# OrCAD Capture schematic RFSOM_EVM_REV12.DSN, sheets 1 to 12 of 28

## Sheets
1 01 POWER_TREE: rev: V1.2
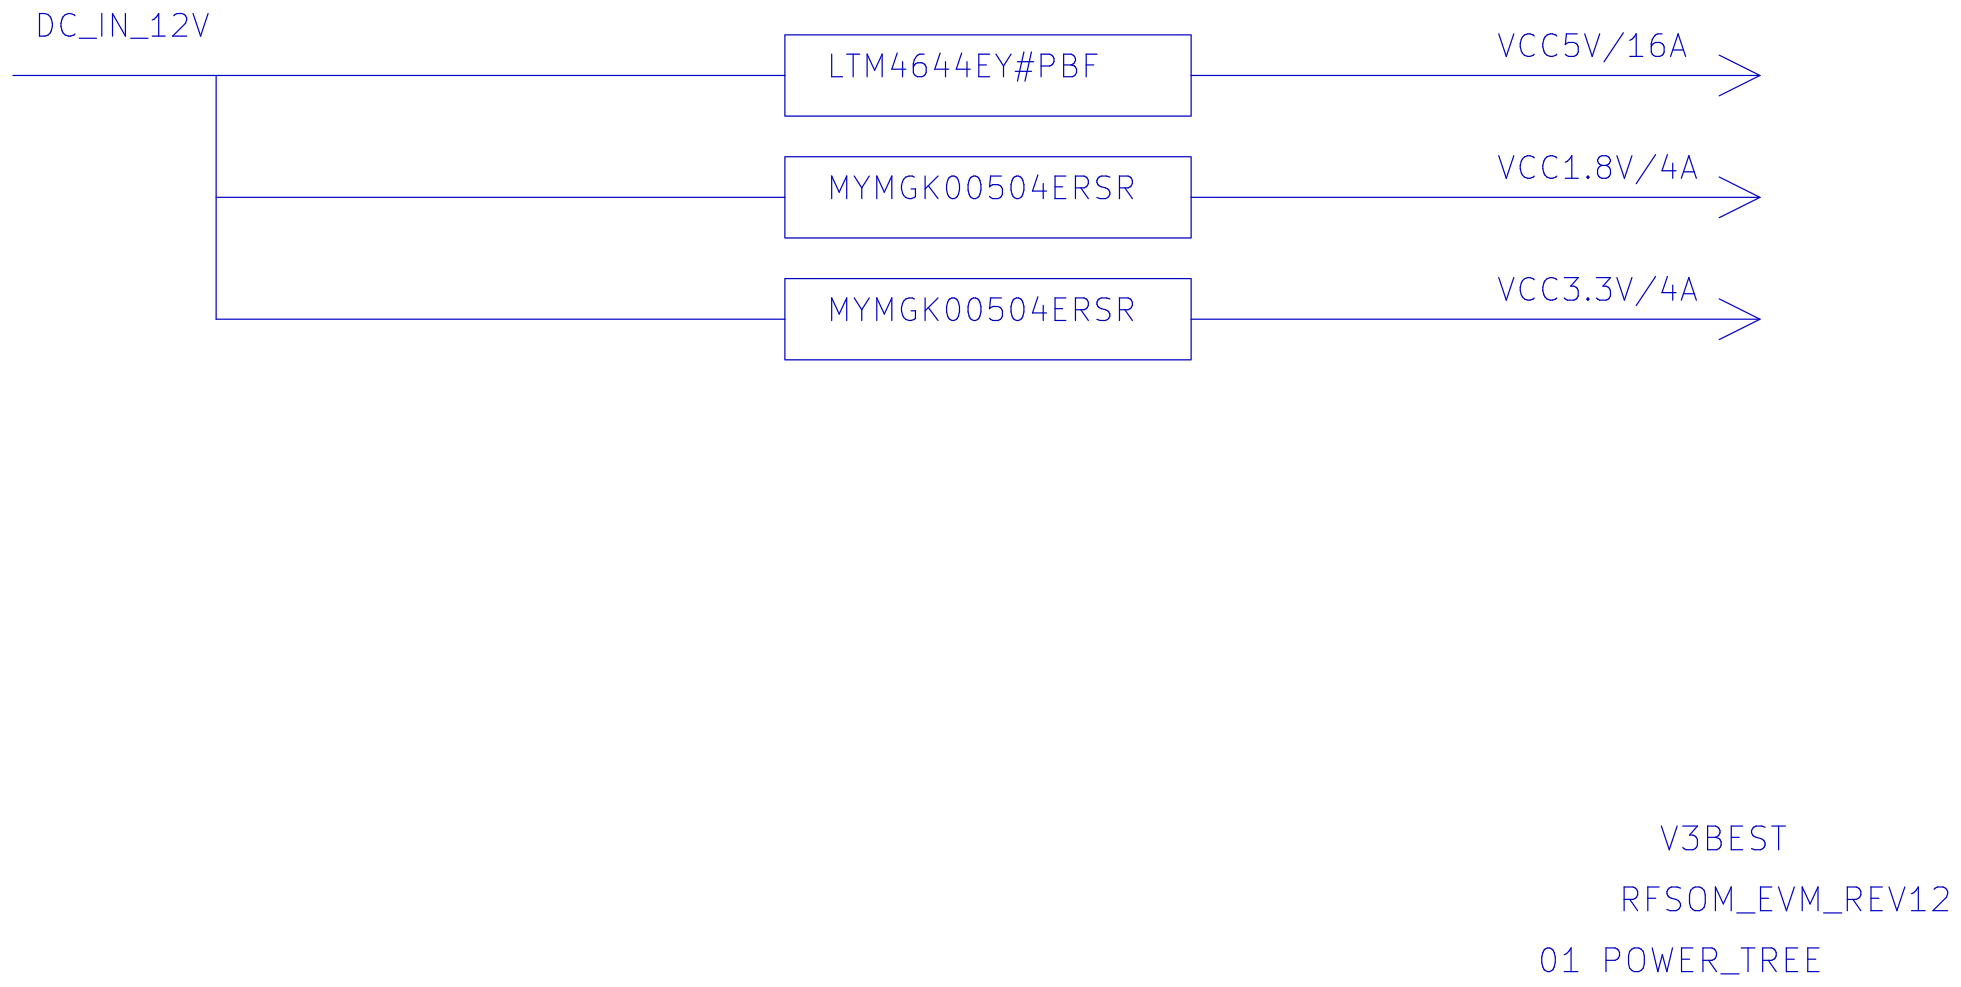
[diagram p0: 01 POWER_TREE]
2 20 ETHERNET: size A4
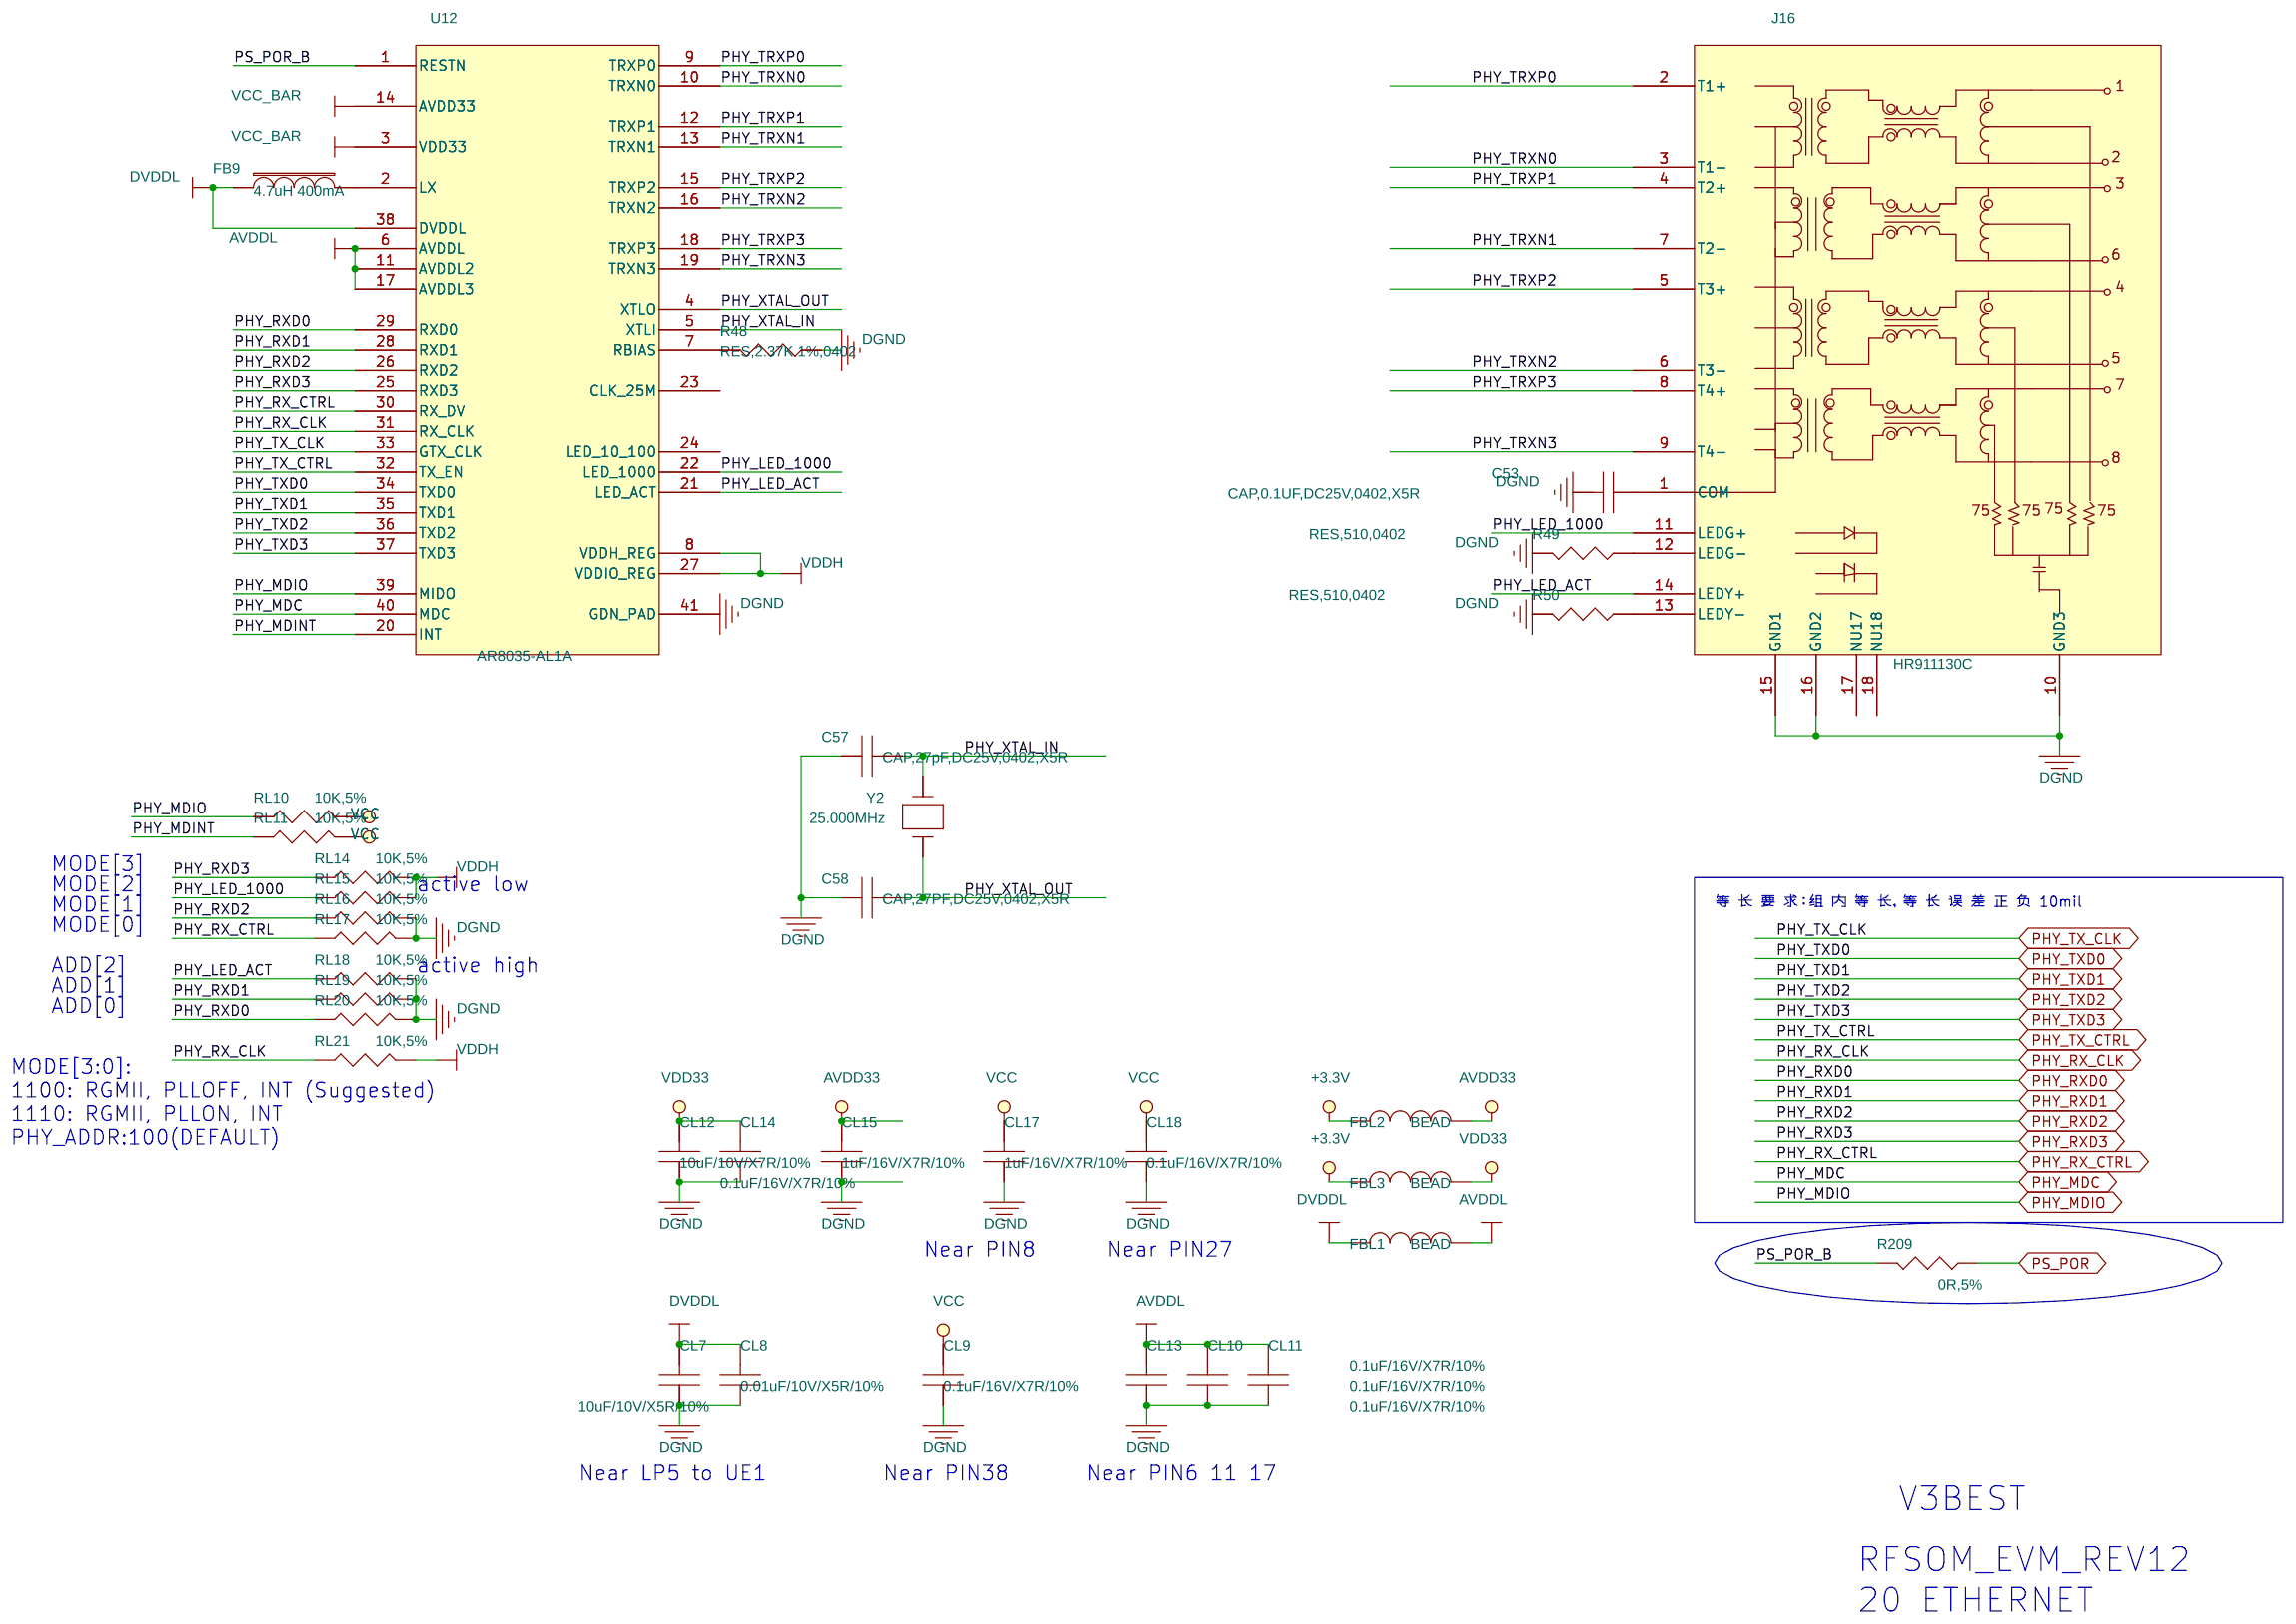
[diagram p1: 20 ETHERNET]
3 19 SFP_SG: size A4
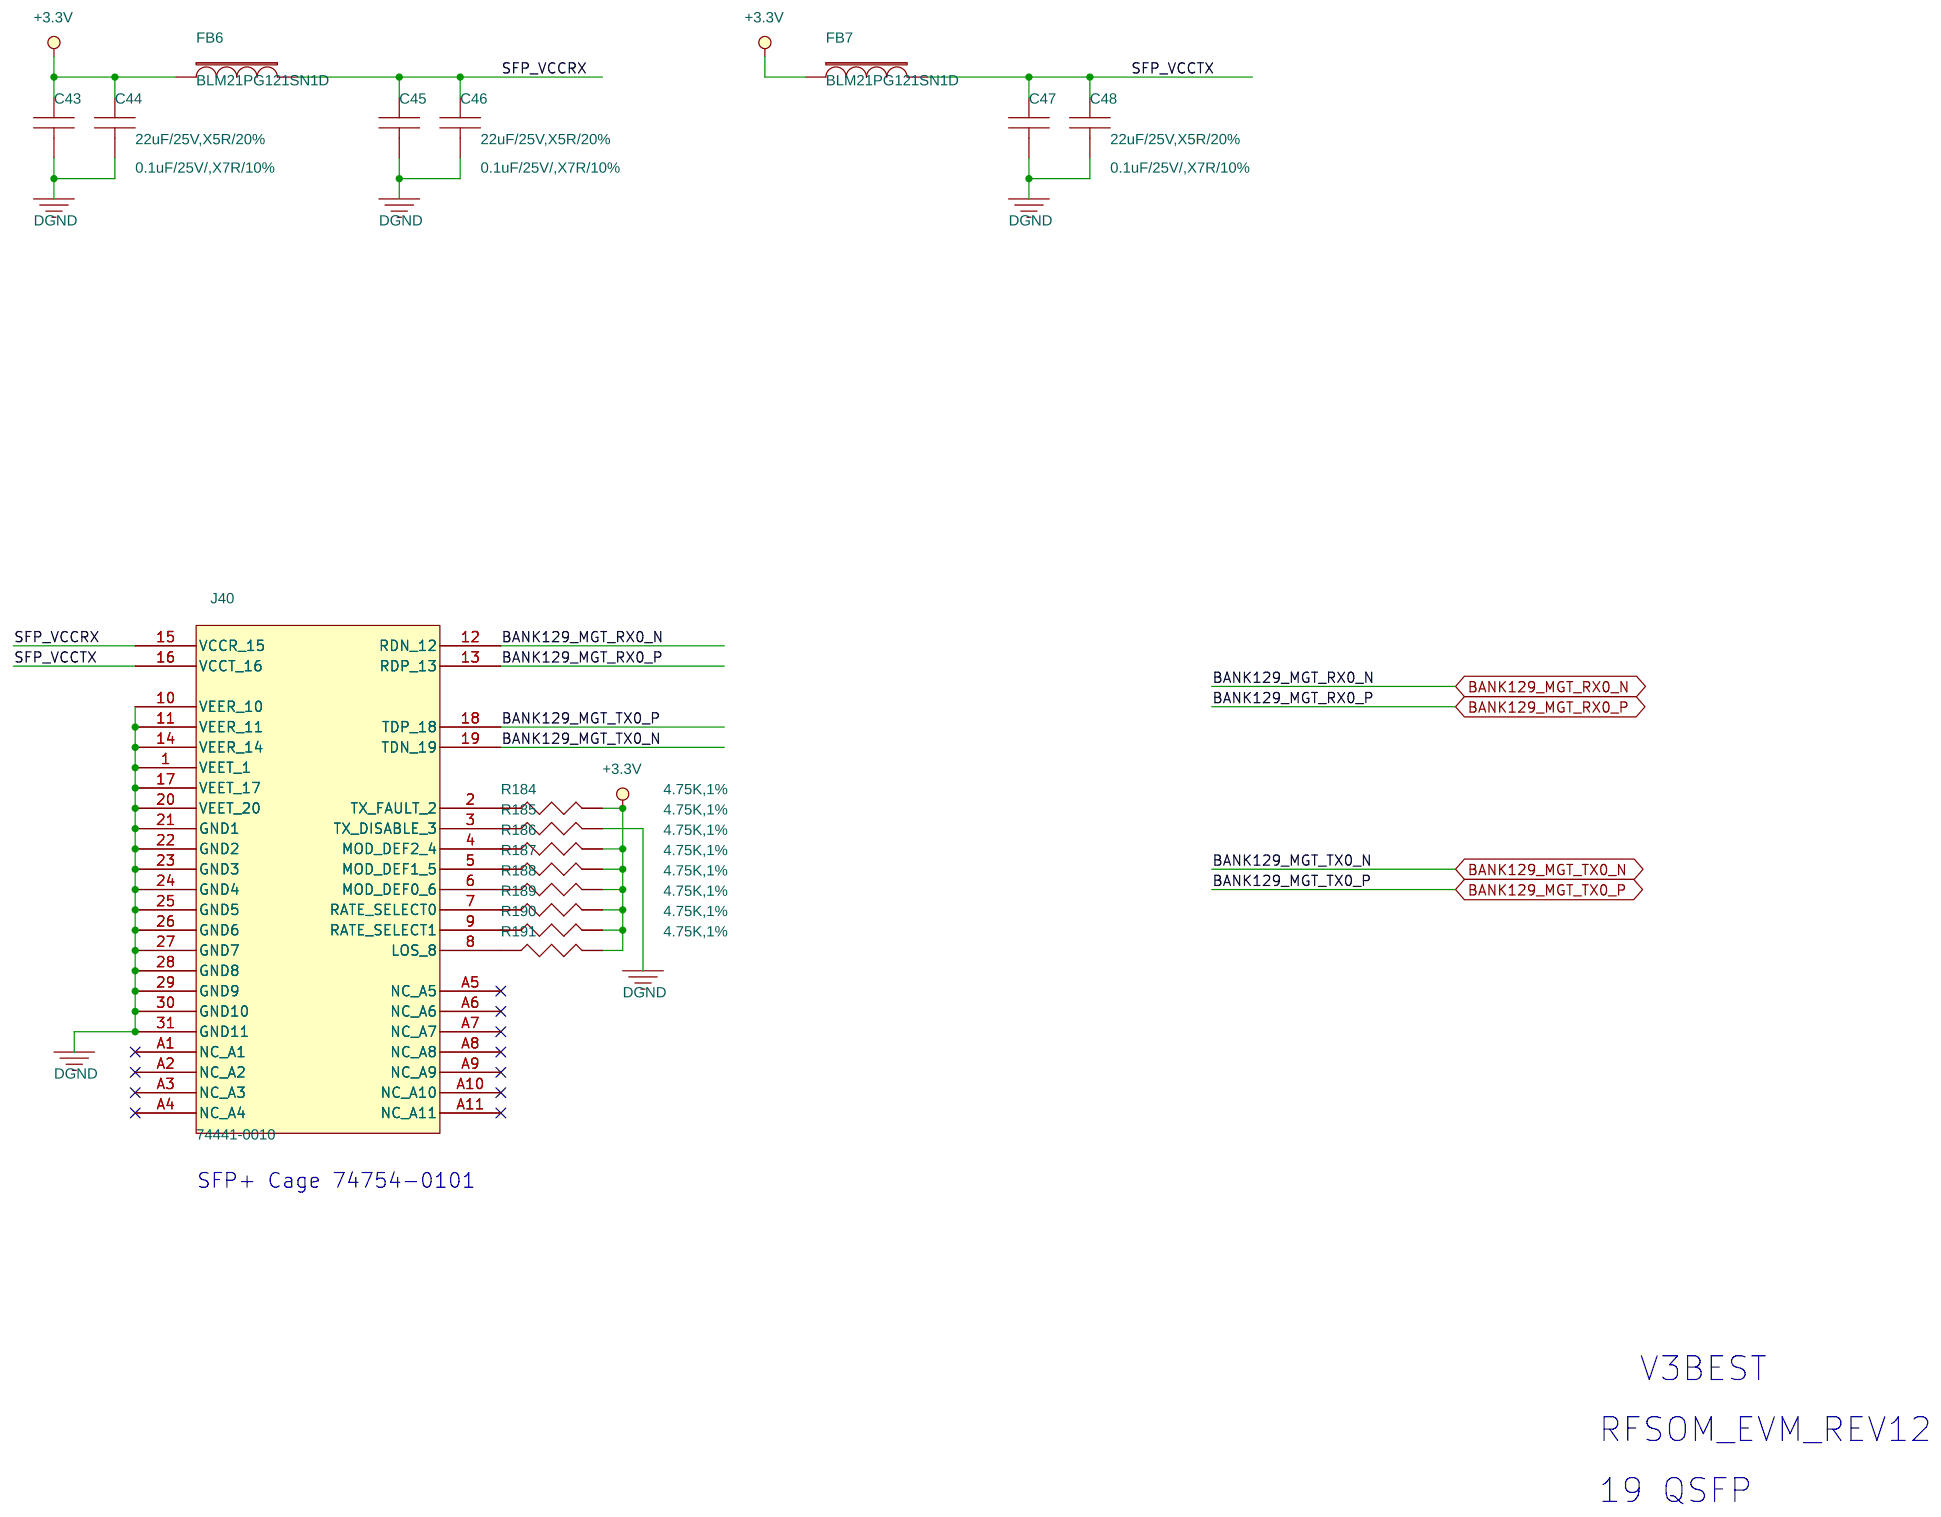
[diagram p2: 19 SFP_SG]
4 27 POWER02: size A4
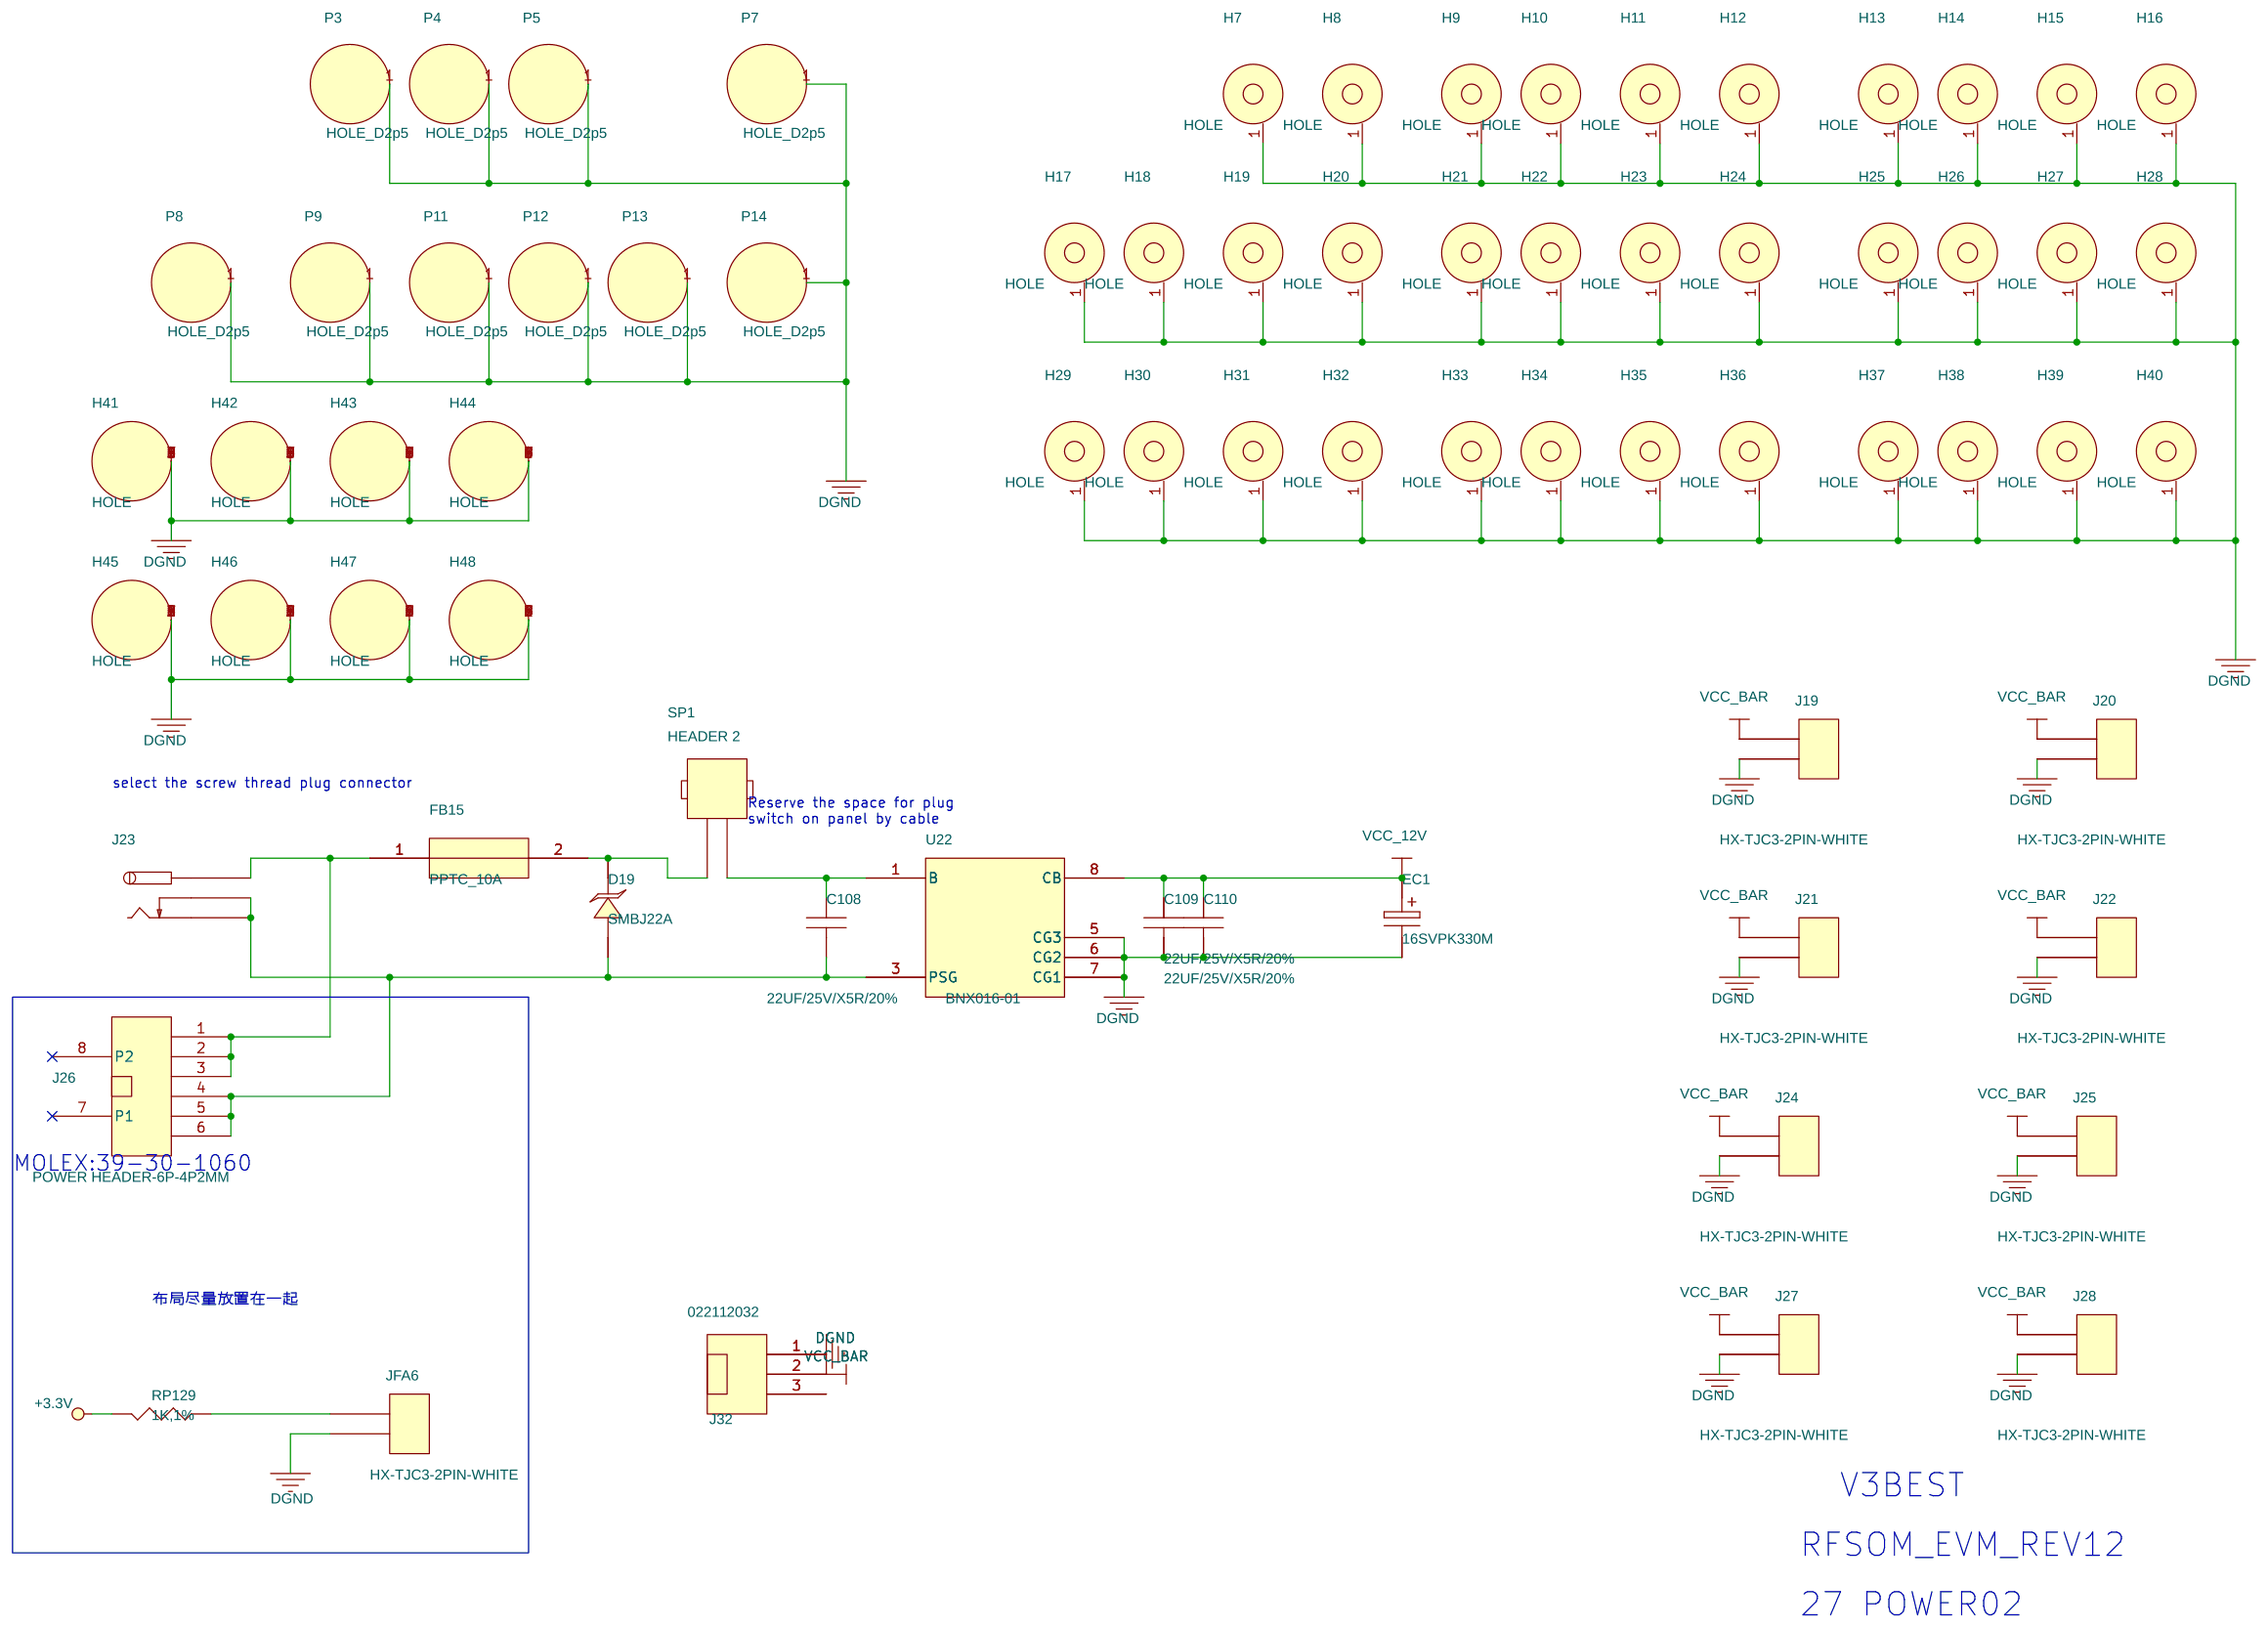
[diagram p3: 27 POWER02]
5 26 POWER01: size A4
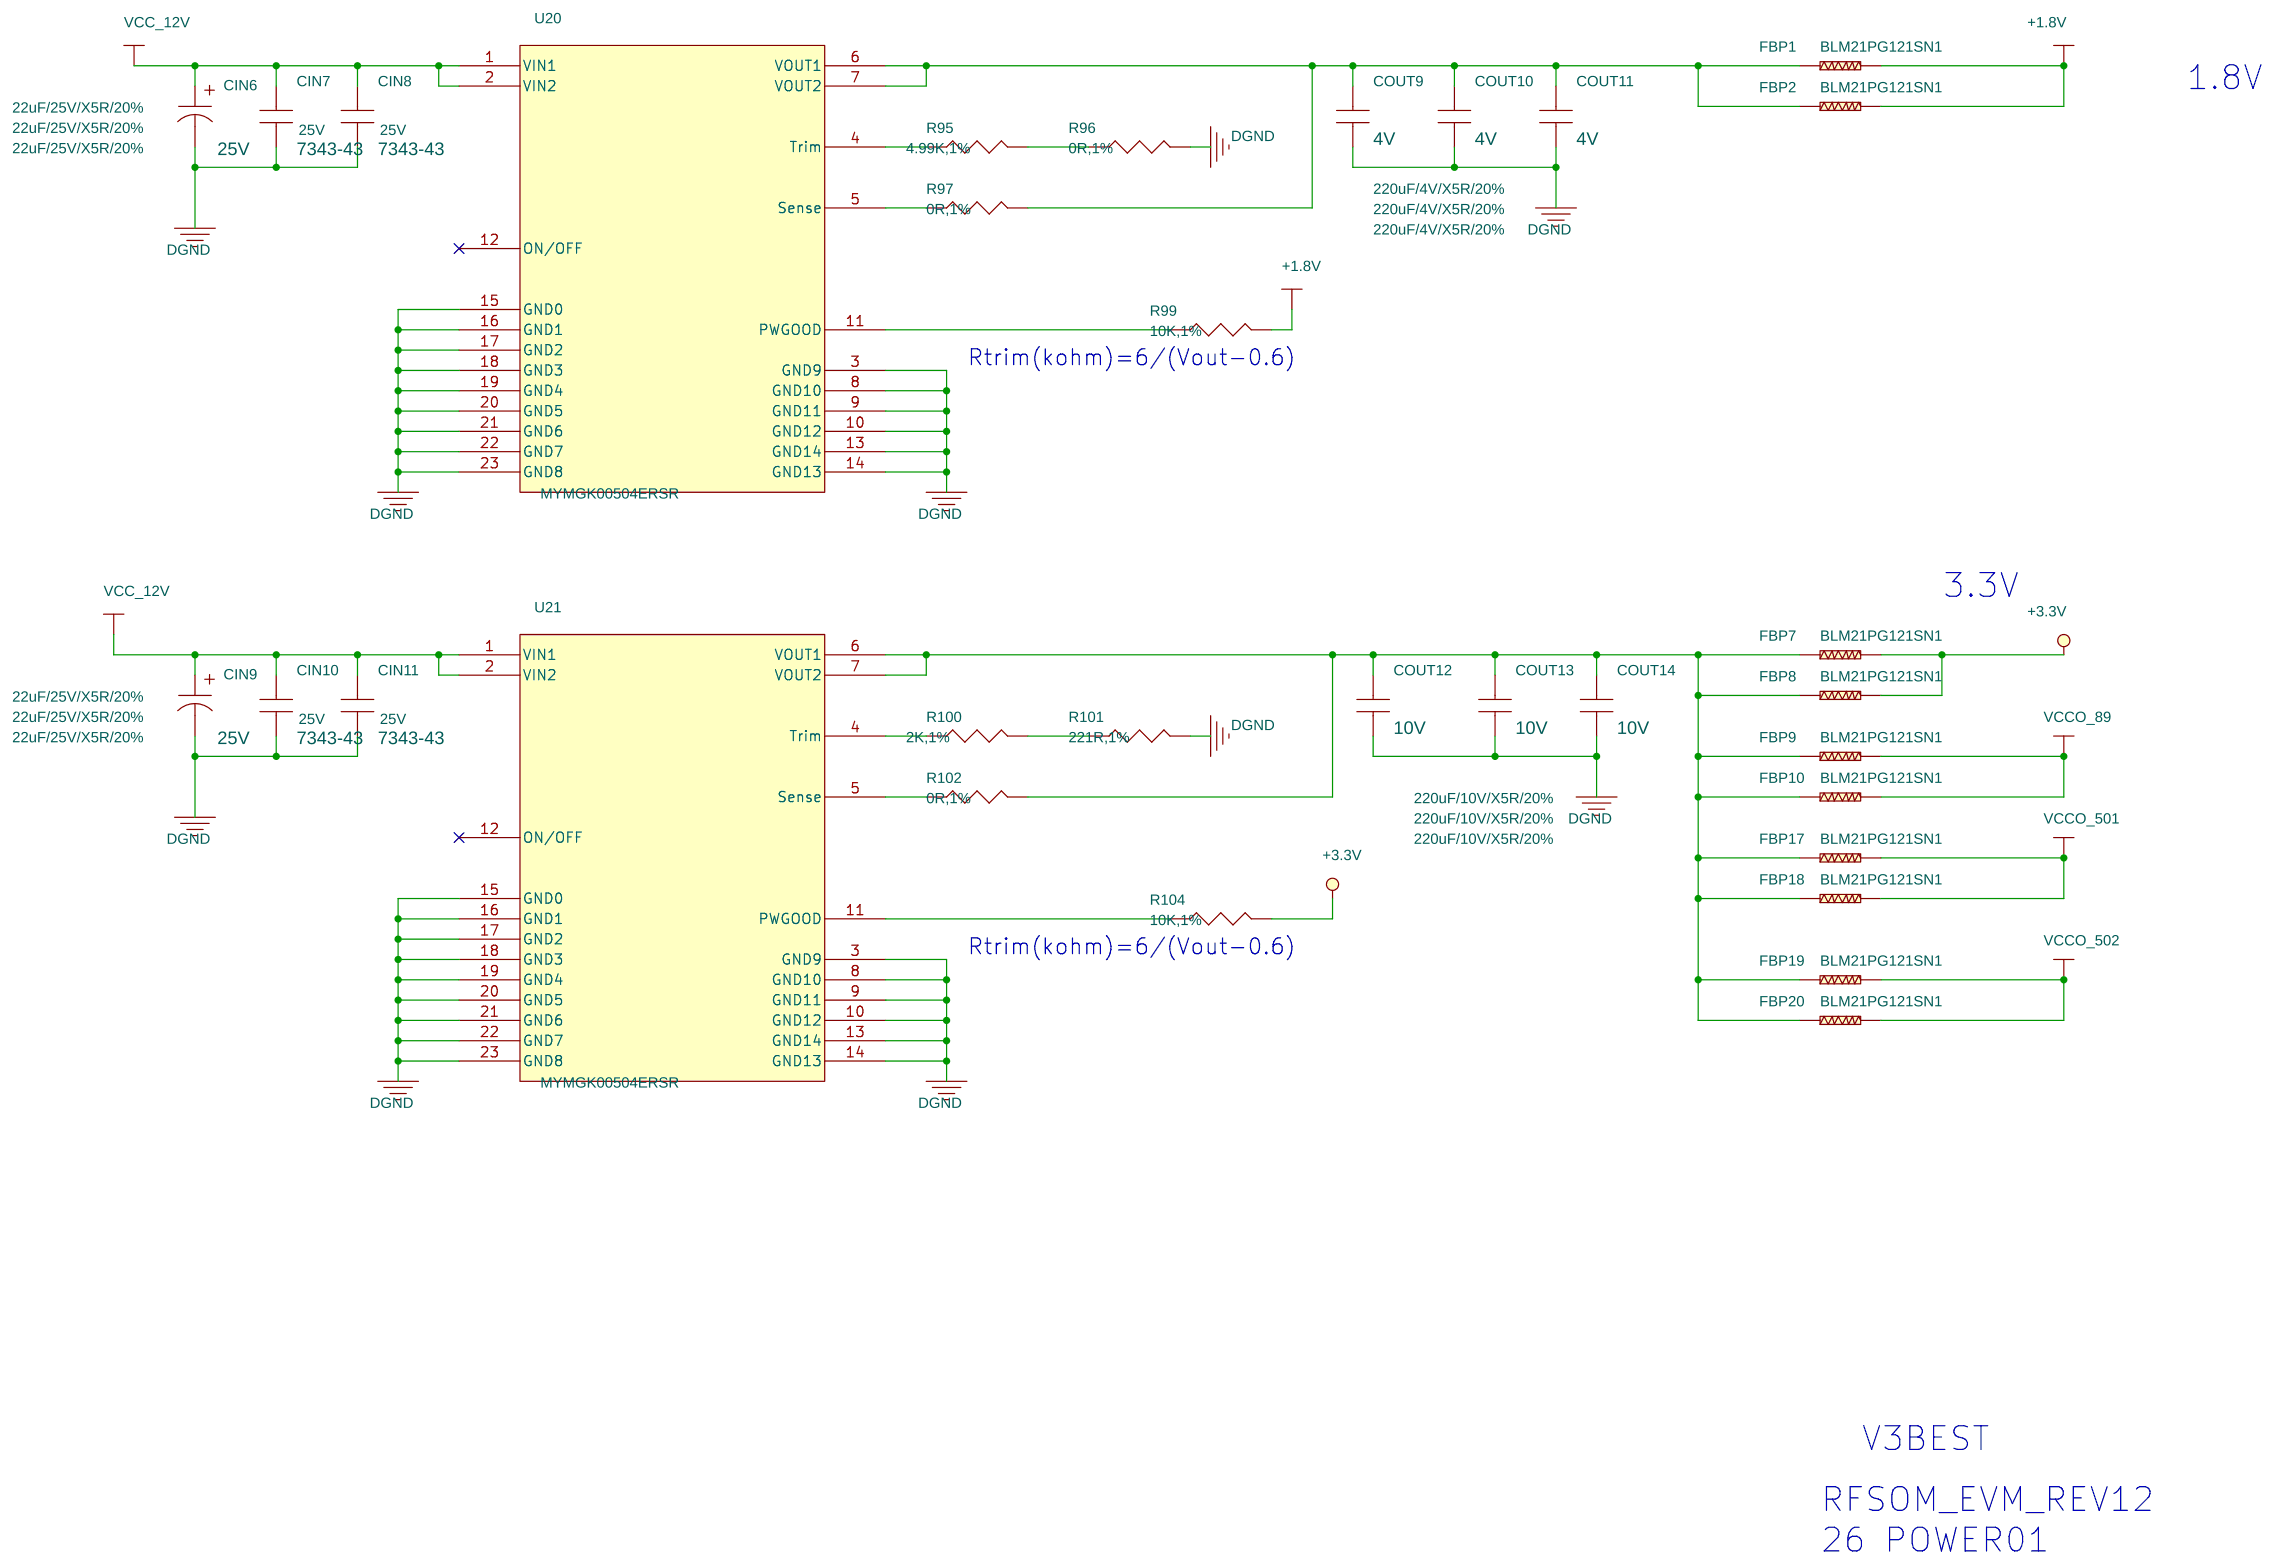
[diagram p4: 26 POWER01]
6 25 POWER00: size A4
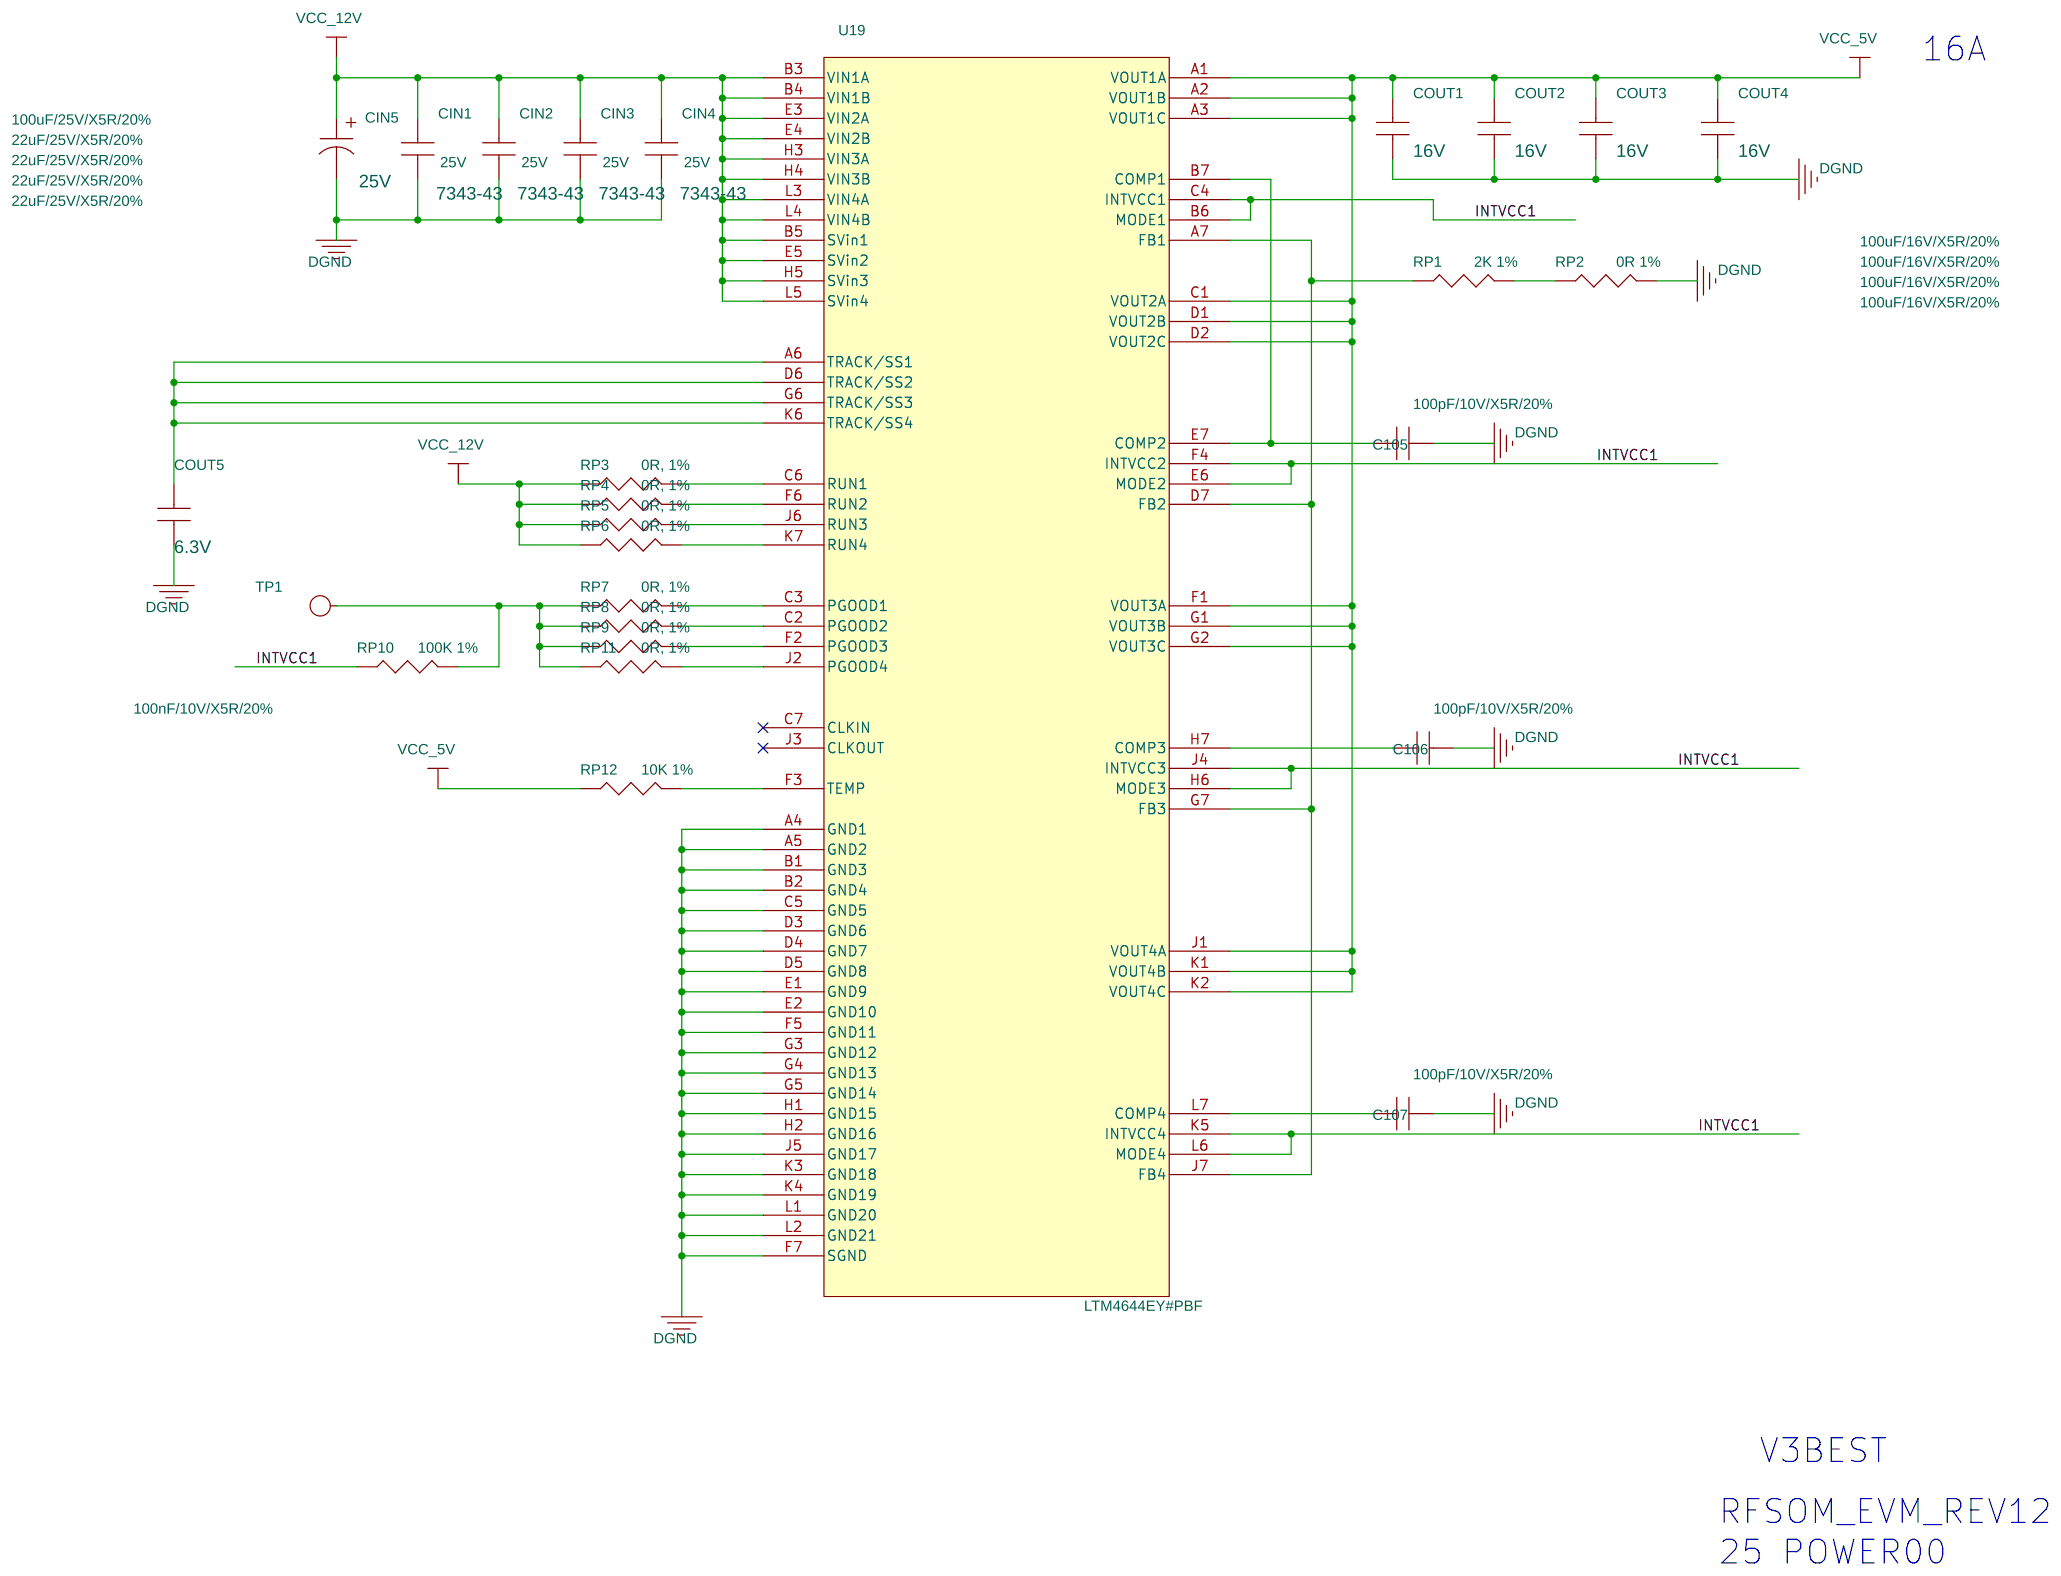
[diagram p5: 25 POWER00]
7 24 TRIG@LED: size A4
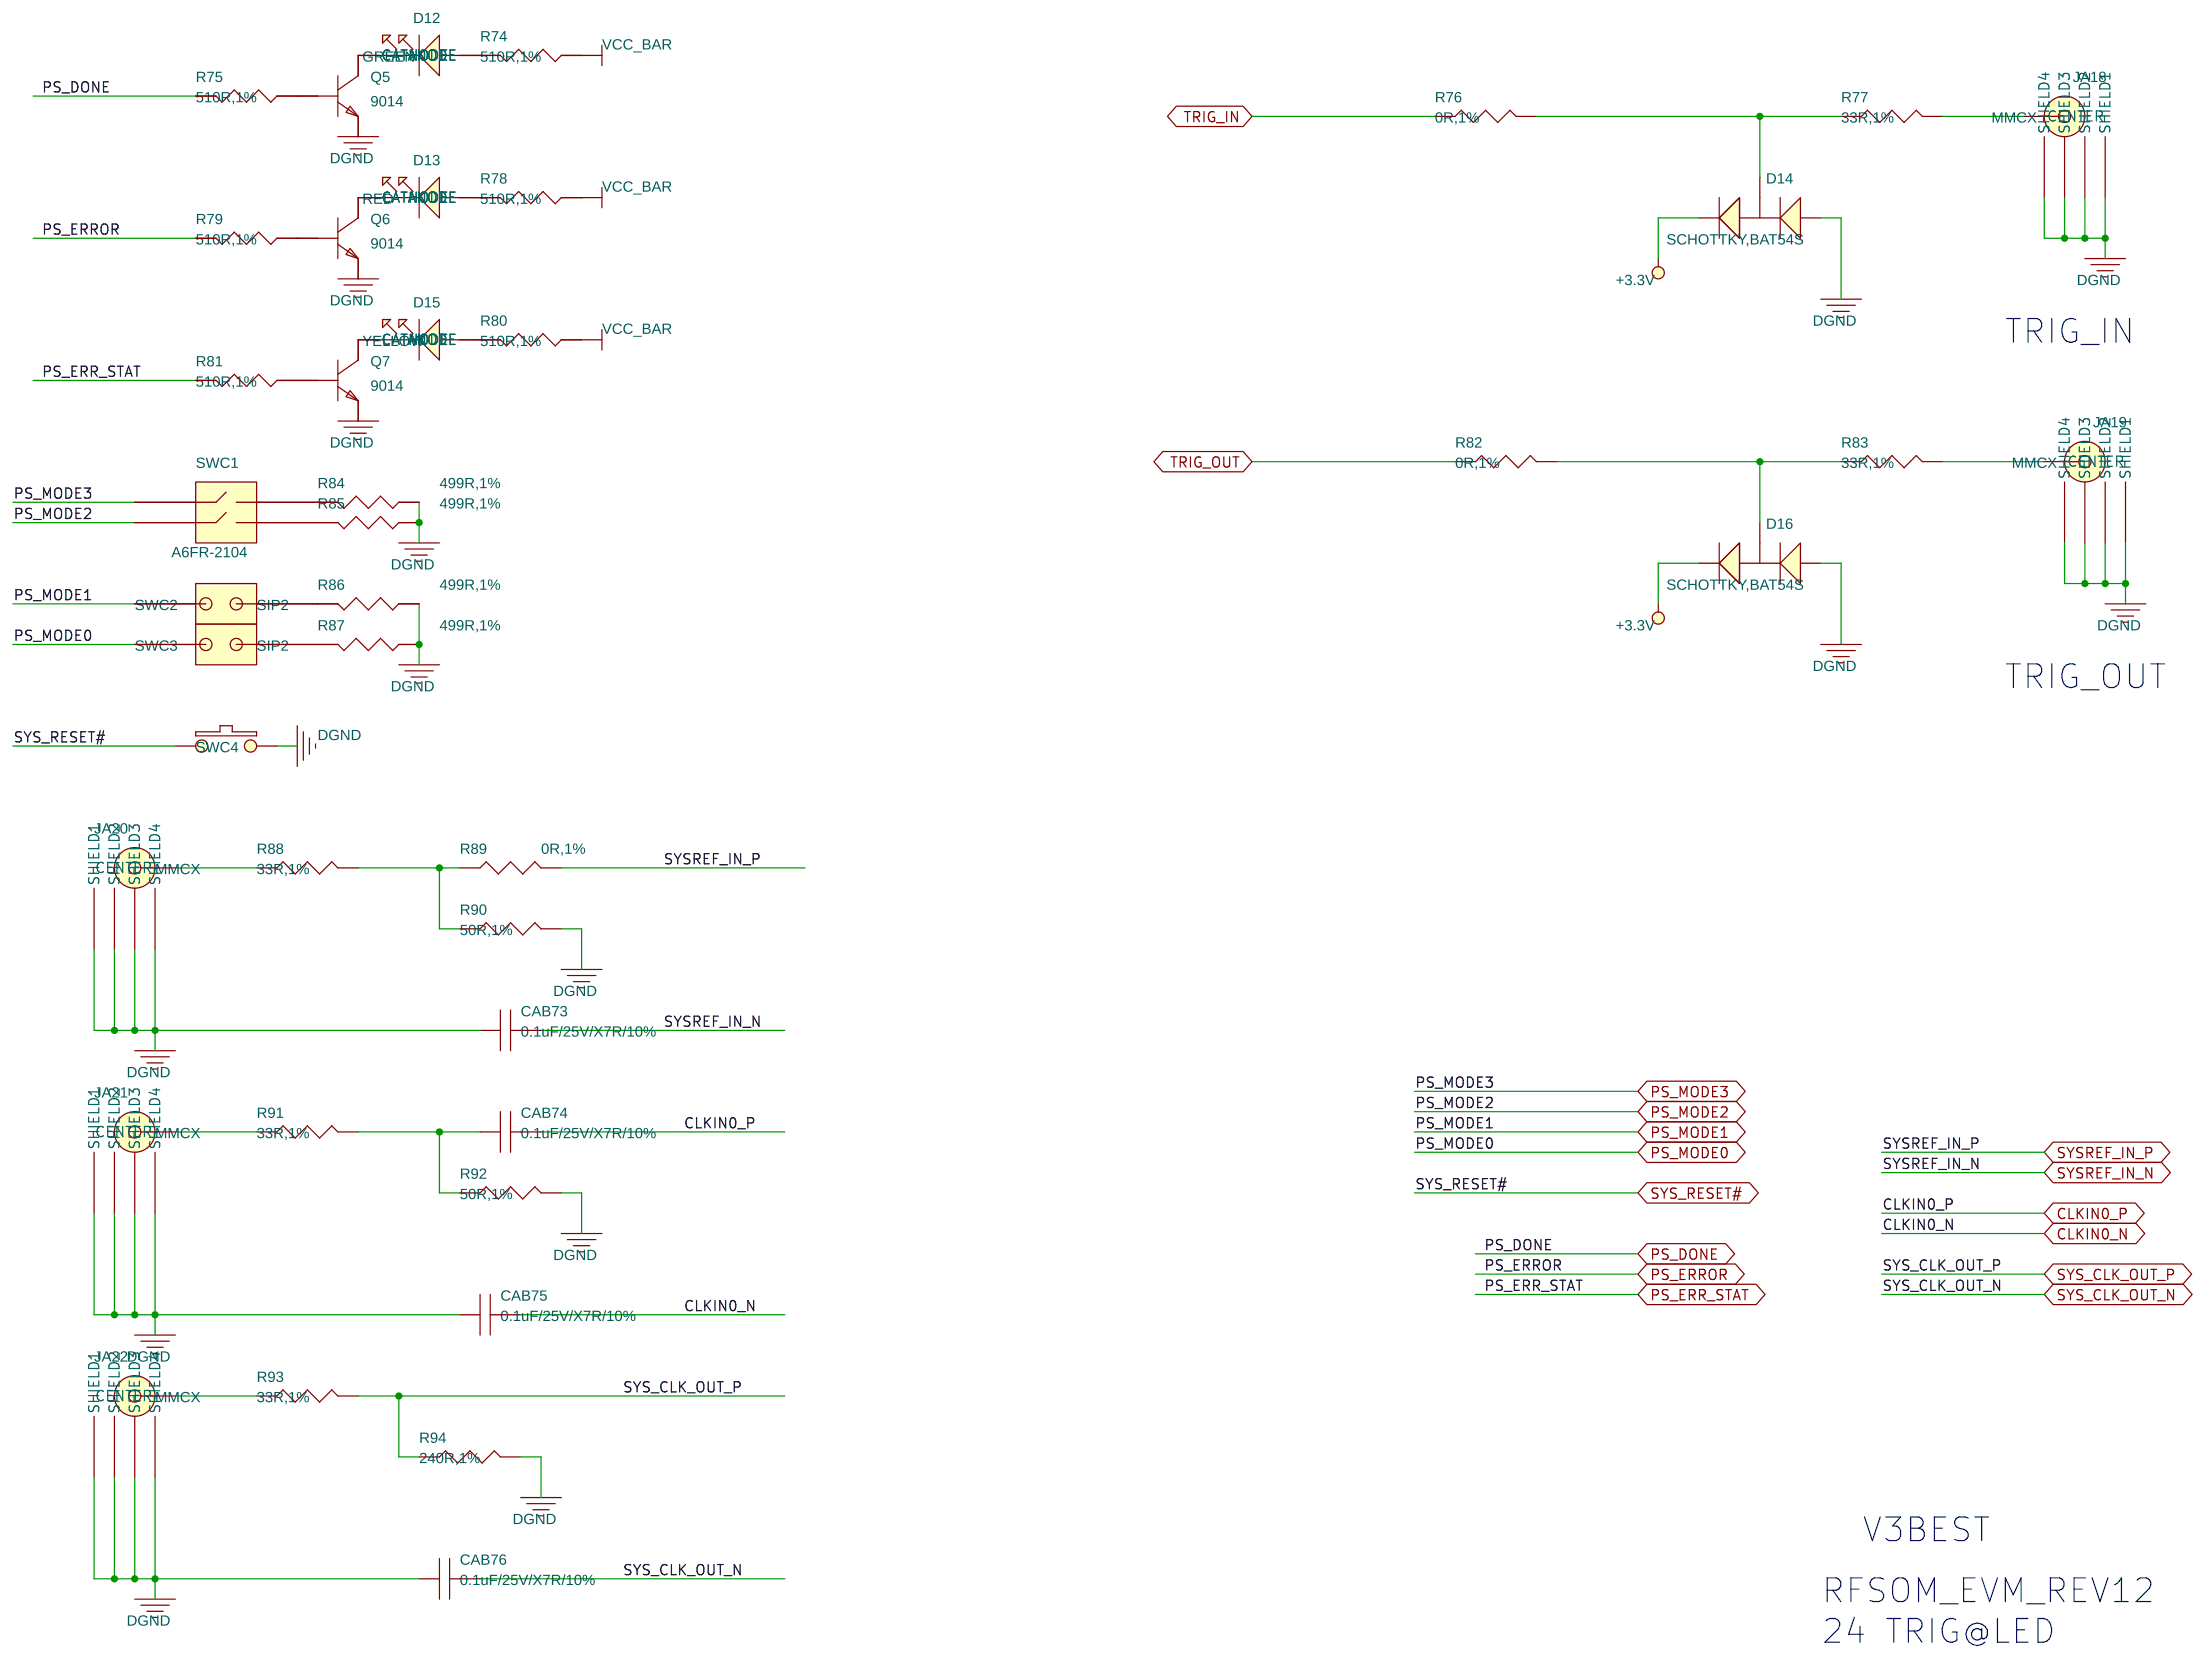
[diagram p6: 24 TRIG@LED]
8 14 RF_RX04: size A4
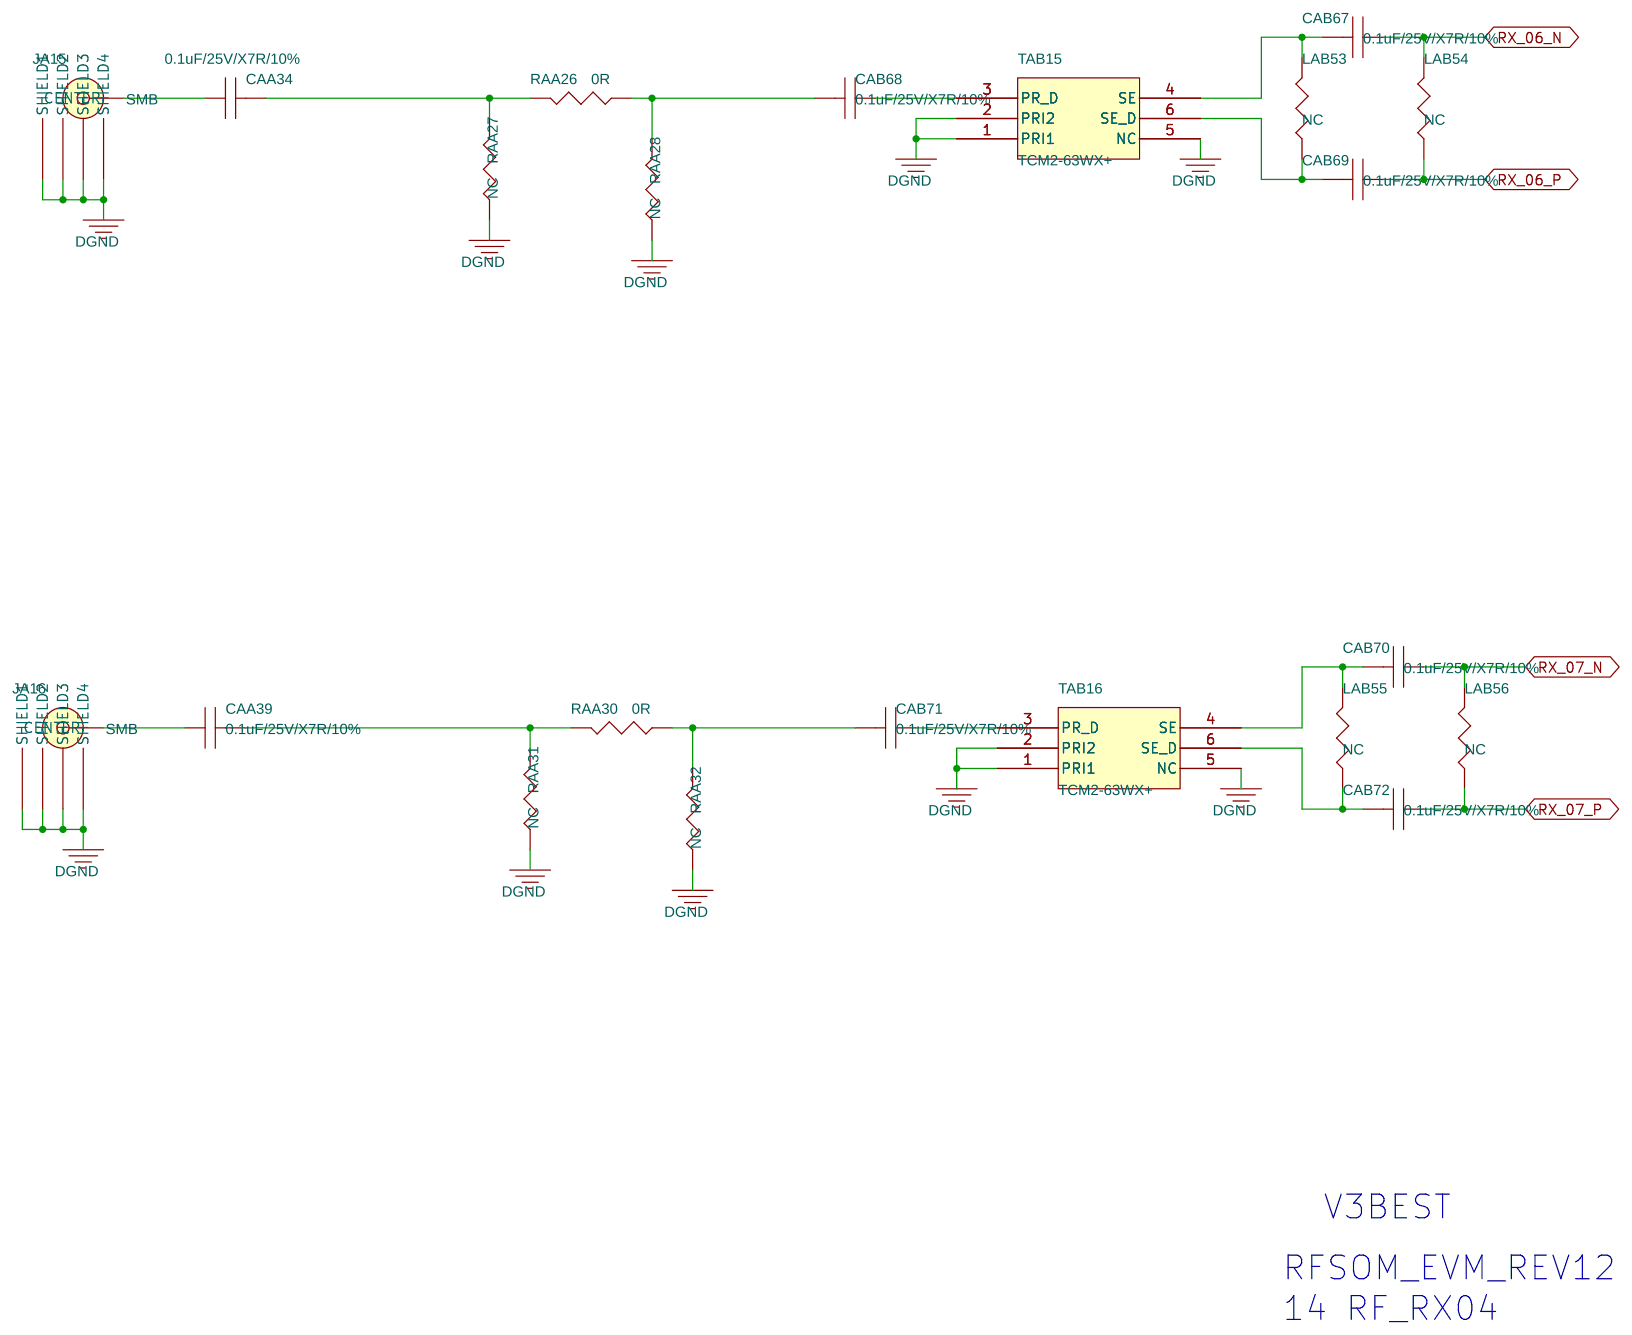
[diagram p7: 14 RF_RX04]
9 13 RF_RX03: size A4
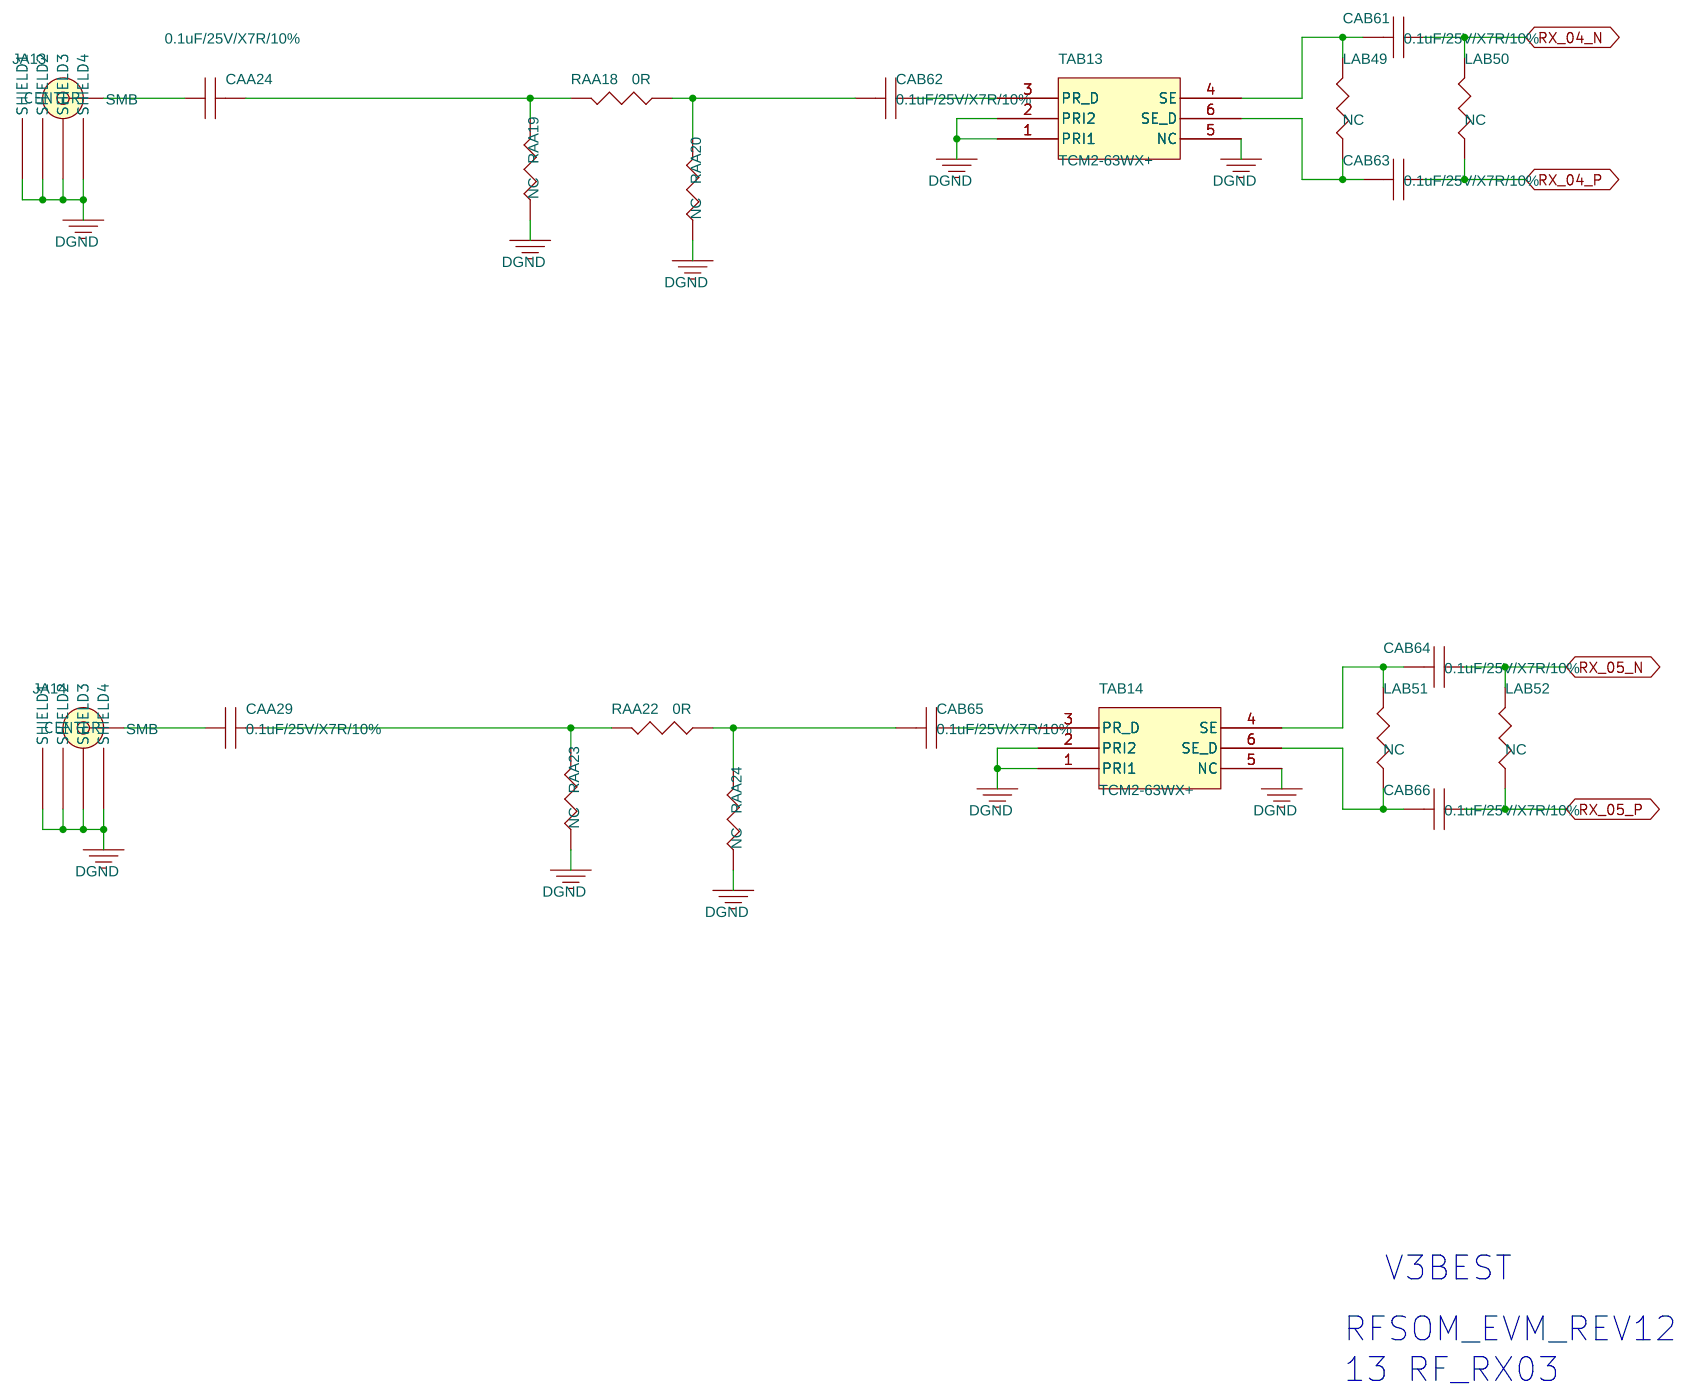
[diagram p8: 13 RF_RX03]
10 12 RF_RX02: size A4
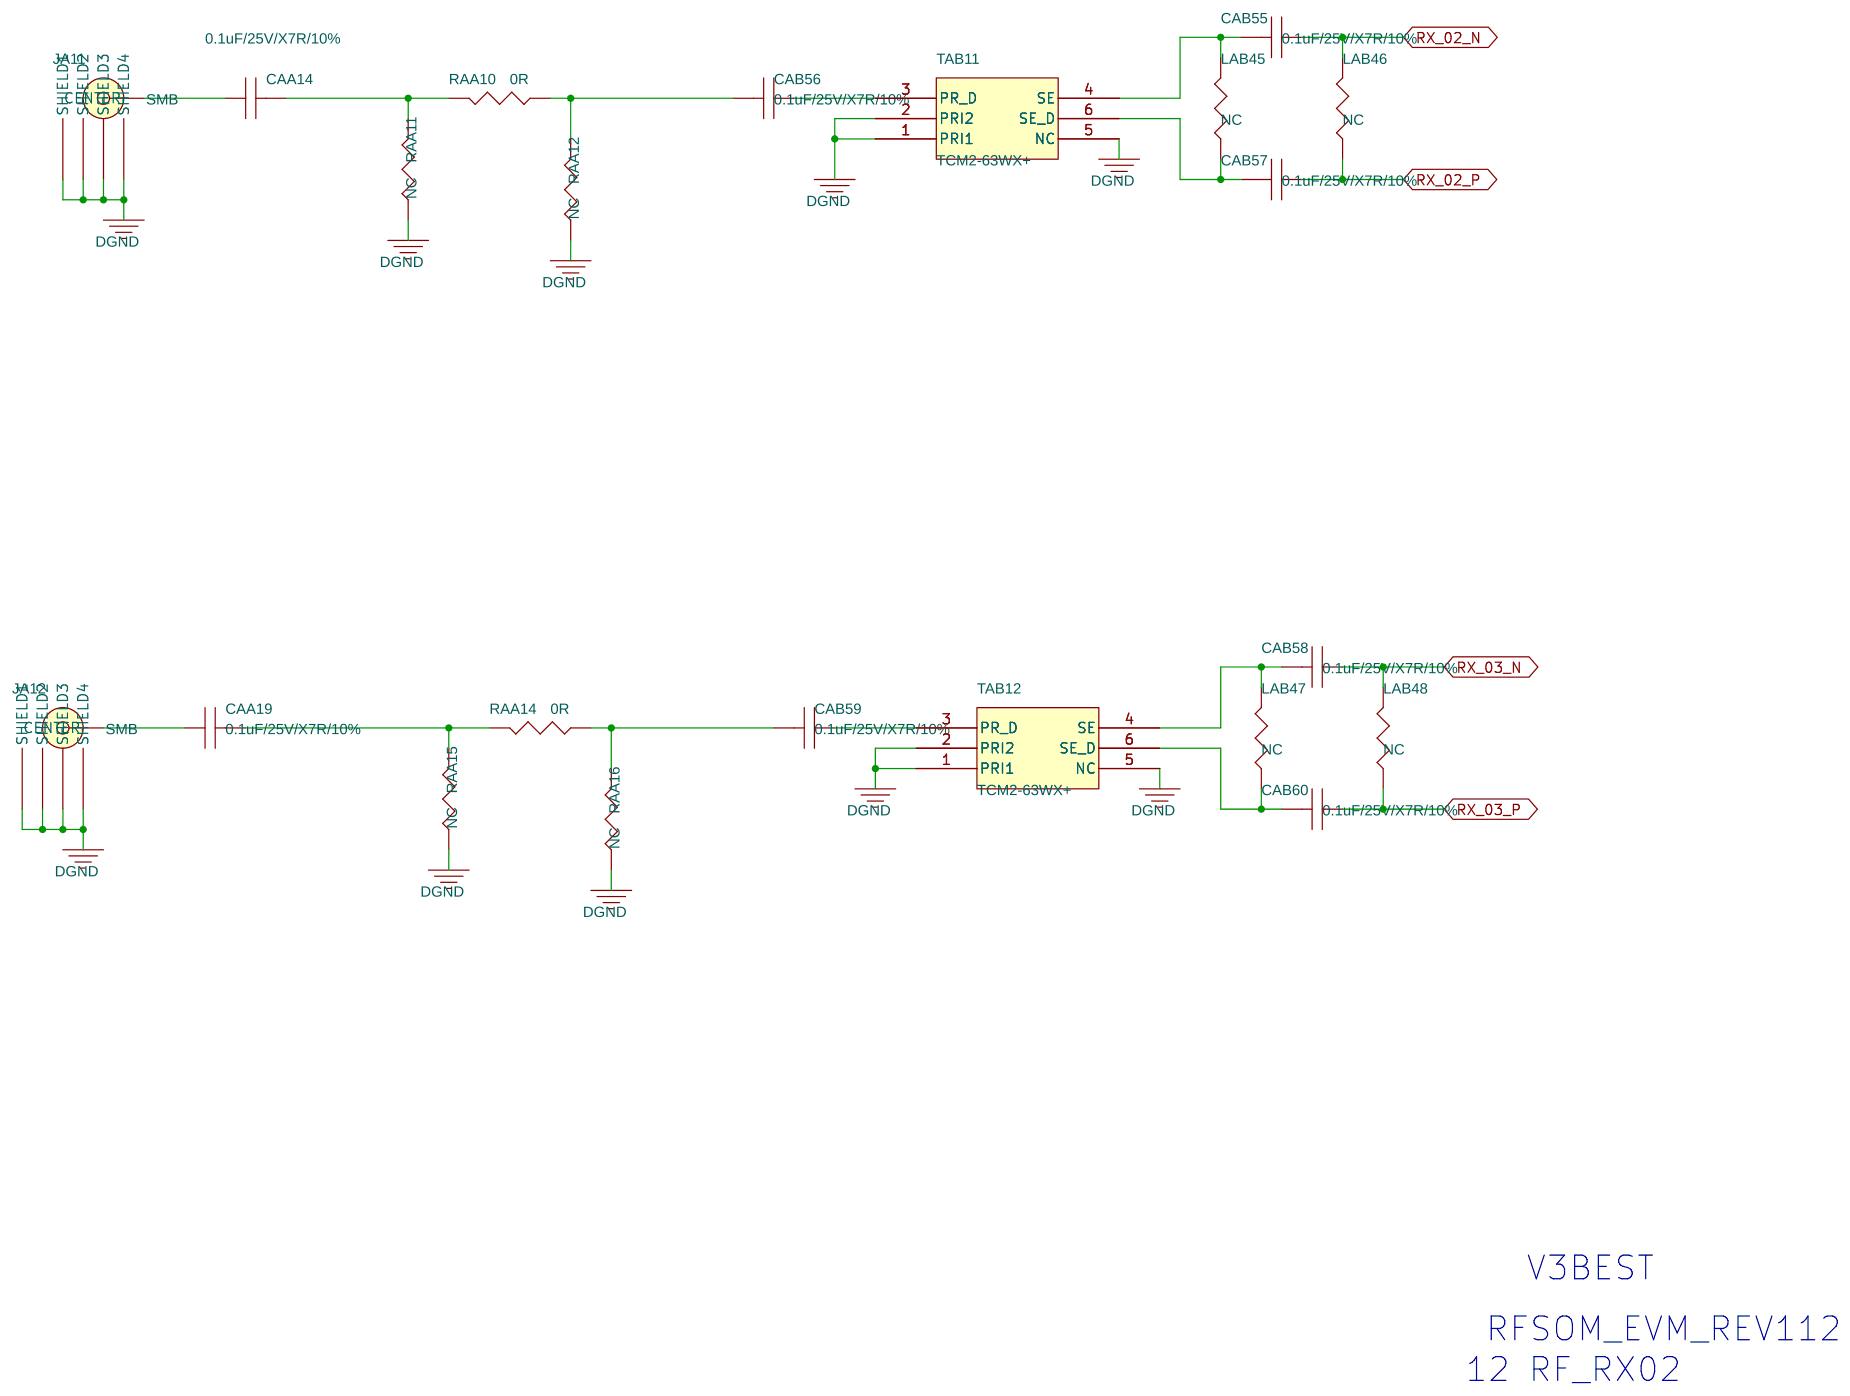
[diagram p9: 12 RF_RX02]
11 11 RF_RX01: size A4
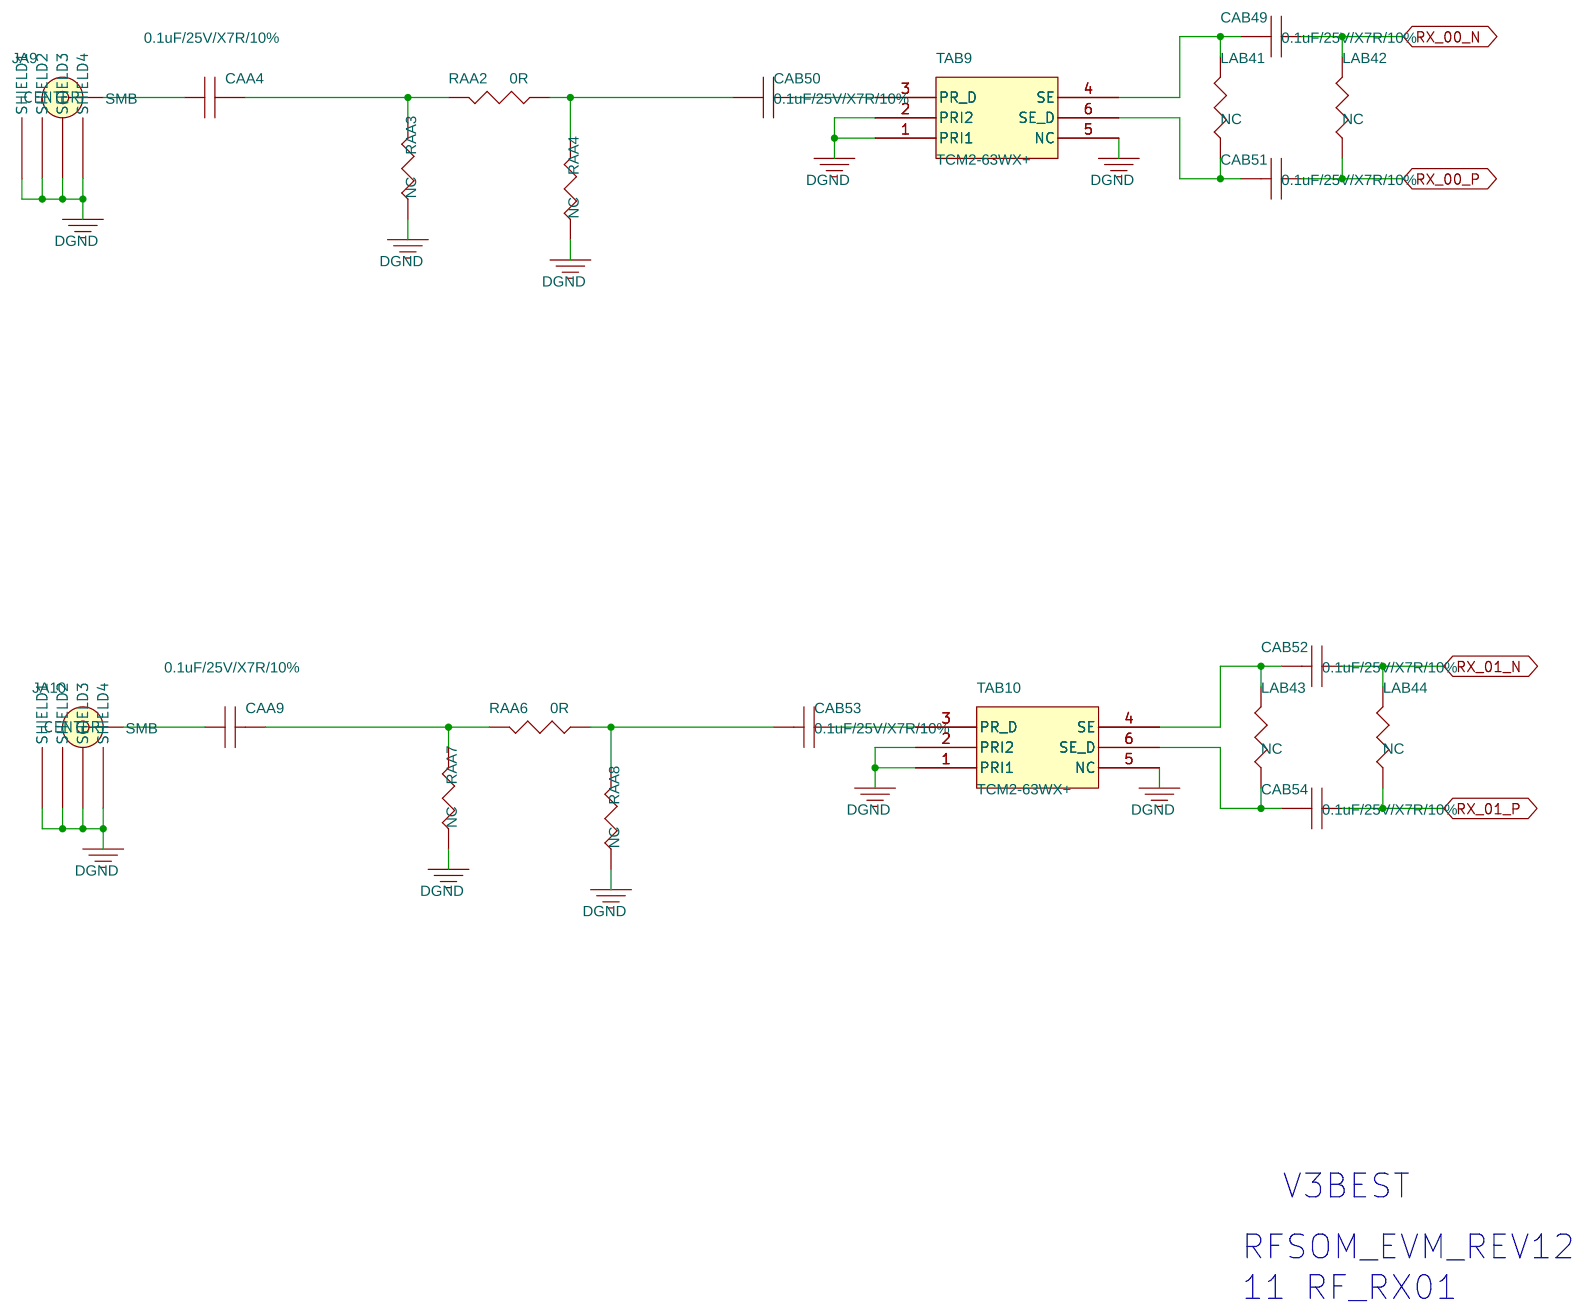
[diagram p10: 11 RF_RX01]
12 10 RF_TX04: size A4
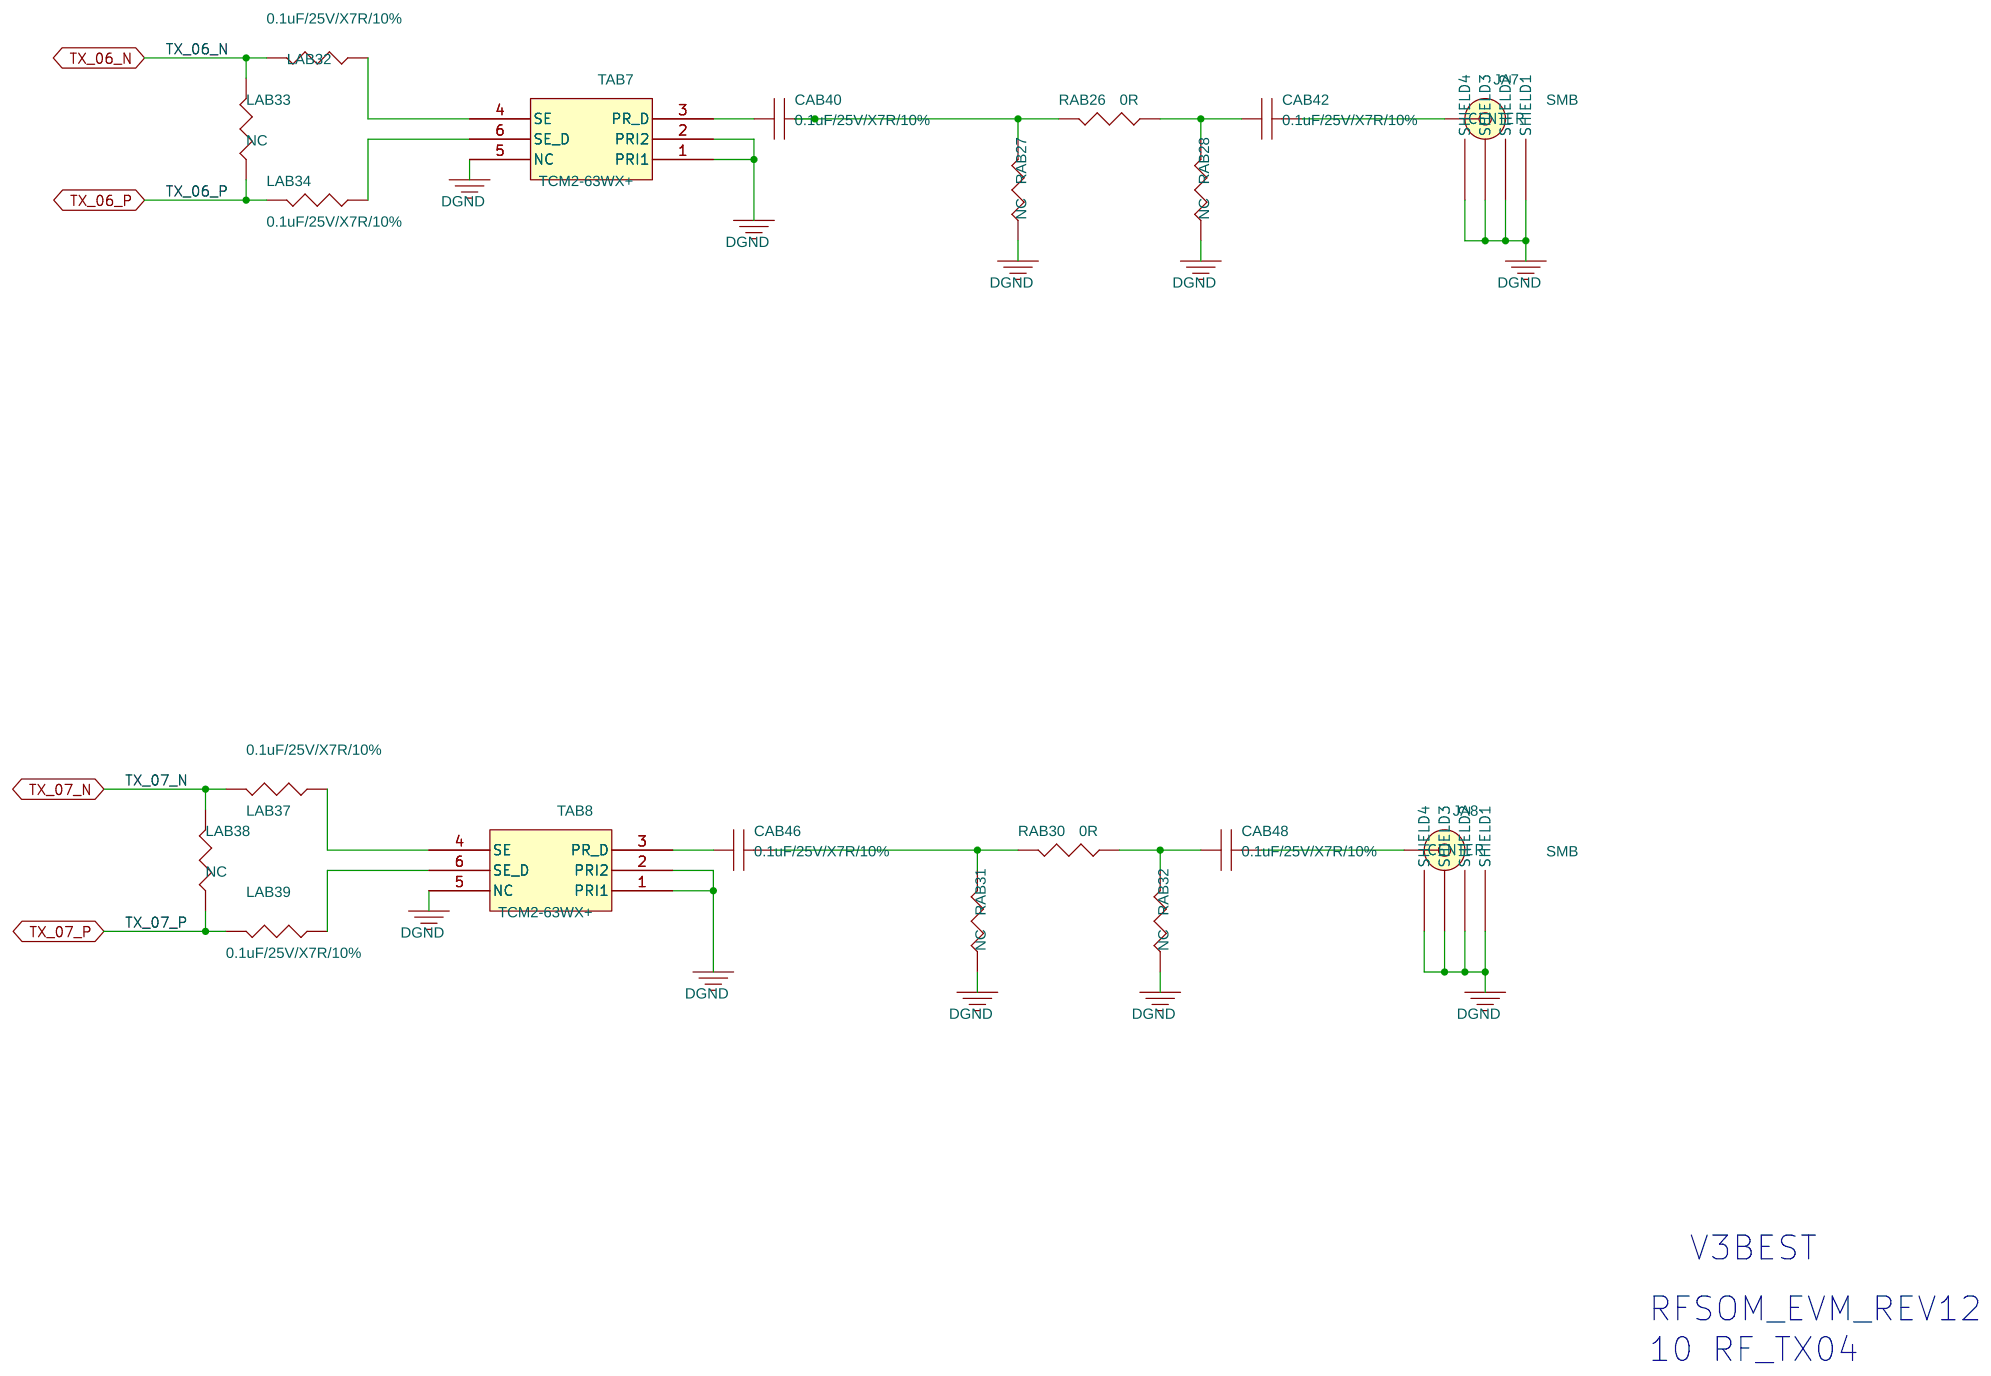
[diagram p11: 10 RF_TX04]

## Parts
sheet 10 RF_TX04
CAB40  0.1uF/25V/X7R/10%  [0402C]
CAB42  0.1uF/25V/X7R/10%  [0402C]
CAB46  0.1uF/25V/X7R/10%  [0402C]
CAB48  0.1uF/25V/X7R/10%  [0402C]
JA7  SMB  [SMB_RF]
JA8  SMB  [SMB_RF]
LAB32  0.1uF/25V/X7R/10%  [0402C]
LAB33  NC  [0402C]
LAB34  0.1uF/25V/X7R/10%  [0402C]
LAB37  0.1uF/25V/X7R/10%  [0402C]
LAB38  NC  [0402C]
LAB39  0.1uF/25V/X7R/10%  [0402C]
RAB26  0R  [0402R]
RAB27  NC  [0402R]
RAB28  NC  [0402R]
RAB30  0R  [0402R]
RAB31  NC  [0402R]
RAB32  NC  [0402R]
TAB7  TCM2-63WX+  [tcm1-63ax_]
TAB8  TCM2-63WX+  [tcm1-63ax_]
sheet 11 RF_RX01
CAA4  0.1uF/25V/X7R/10%  [0402C]
CAA9  0.1uF/25V/X7R/10%  [0402C]
CAB49  0.1uF/25V/X7R/10%  [0402C]
CAB50  0.1uF/25V/X7R/10%  [0402C]
CAB51  0.1uF/25V/X7R/10%  [0402C]
CAB52  0.1uF/25V/X7R/10%  [0402C]
CAB53  0.1uF/25V/X7R/10%  [0402C]
CAB54  0.1uF/25V/X7R/10%  [0402C]
JA9  SMB  [SMB_RF]
JA10  SMB  [SMB_RF]
LAB41  NC  [0402C]
LAB42  NC  [0402C]
LAB43  NC  [0402C]
LAB44  NC  [0402C]
RAA2  0R  [0402R]
RAA3  NC  [0402R]
RAA4  NC  [0402R]
RAA6  0R  [0402R]
RAA7  NC  [0402R]
RAA8  NC  [0402R]
TAB9  TCM2-63WX+  [tcm1-63ax_]
TAB10  TCM2-63WX+  [tcm1-63ax_]
sheet 12 RF_RX02
CAA14  0.1uF/25V/X7R/10%  [0402C]
CAA19  0.1uF/25V/X7R/10%  [0402C]
CAB55  0.1uF/25V/X7R/10%  [0402C]
CAB56  0.1uF/25V/X7R/10%  [0402C]
CAB57  0.1uF/25V/X7R/10%  [0402C]
CAB58  0.1uF/25V/X7R/10%  [0402C]
CAB59  0.1uF/25V/X7R/10%  [0402C]
CAB60  0.1uF/25V/X7R/10%  [0402C]
JA11  SMB  [SMB_RF]
JA12  SMB  [SMB_RF]
LAB45  NC  [0402C]
LAB46  NC  [0402C]
LAB47  NC  [0402C]
LAB48  NC  [0402C]
RAA10  0R  [0402R]
RAA11  NC  [0402R]
RAA12  NC  [0402R]
RAA14  0R  [0402R]
RAA15  NC  [0402R]
RAA16  NC  [0402R]
TAB11  TCM2-63WX+  [tcm1-63ax_]
TAB12  TCM2-63WX+  [tcm1-63ax_]
sheet 13 RF_RX03
CAA24  0.1uF/25V/X7R/10%  [0402C]
CAA29  0.1uF/25V/X7R/10%  [0402C]
CAB61  0.1uF/25V/X7R/10%  [0402C]
CAB62  0.1uF/25V/X7R/10%  [0402C]
CAB63  0.1uF/25V/X7R/10%  [0402C]
CAB64  0.1uF/25V/X7R/10%  [0402C]
CAB65  0.1uF/25V/X7R/10%  [0402C]
CAB66  0.1uF/25V/X7R/10%  [0402C]
JA13  SMB  [SMB_RF]
JA14  SMB  [SMB_RF]
LAB49  NC  [0402C]
LAB50  NC  [0402C]
LAB51  NC  [0402C]
LAB52  NC  [0402C]
RAA18  0R  [0402R]
RAA19  NC  [0402R]
RAA20  NC  [0402R]
RAA22  0R  [0402R]
RAA23  NC  [0402R]
RAA24  NC  [0402R]
TAB13  TCM2-63WX+  [tcm1-63ax_]
TAB14  TCM2-63WX+  [tcm1-63ax_]
sheet 14 RF_RX04
CAA34  0.1uF/25V/X7R/10%  [0402C]
CAA39  0.1uF/25V/X7R/10%  [0402C]
CAB67  0.1uF/25V/X7R/10%  [0402C]
CAB68  0.1uF/25V/X7R/10%  [0402C]
CAB69  0.1uF/25V/X7R/10%  [0402C]
CAB70  0.1uF/25V/X7R/10%  [0402C]
CAB71  0.1uF/25V/X7R/10%  [0402C]
CAB72  0.1uF/25V/X7R/10%  [0402C]
JA15  SMB  [SMB_RF]
JA16  SMB  [SMB_RF]
LAB53  NC  [0402C]
LAB54  NC  [0402C]
LAB55  NC  [0402C]
LAB56  NC  [0402C]
RAA26  0R  [0402R]
RAA27  NC  [0402R]
RAA28  NC  [0402R]
RAA30  0R  [0402R]
RAA31  NC  [0402R]
RAA32  NC  [0402R]
TAB15  TCM2-63WX+  [tcm1-63ax_]
TAB16  TCM2-63WX+  [tcm1-63ax_]
sheet 19 SFP_SG
C43  22uF/25V,X5R/20%  [C1206]
C44  0.1uF/25V/,X7R/10%  [C0402]
C45  22uF/25V,X5R/20%  [C1206]
C46  0.1uF/25V/,X7R/10%  [C0402]
C47  22uF/25V,X5R/20%  [C1206]
C48  0.1uF/25V/,X7R/10%  [C0402]
FB6  BLM21PG121SN1D  [FB0805]
FB7  BLM21PG121SN1D  [FB0805]
J40  74441-0010  [SFP_MODULE]
R184  4.75K,1%  [R0402]
R185  4.75K,1%  [R0402]
R186  4.75K,1%  [R0402]
R187  4.75K,1%  [R0402]
R188  4.75K,1%  [R0402]
R189  4.75K,1%  [R0402]
R190  4.75K,1%  [R0402]
R191  4.75K,1%  [R0402]
sheet 20 ETHERNET
C53  CAP,0.1UF,DC25V,0402,X5R  [C0402-BGA]
C57  CAP,27pF,DC25V,0402,X5R  [C0402-BGA]
C58  CAP,27PF,DC25V,0402,X5R  [C0402-BGA]
CL7  10uF/10V/X5R/10%  [0402C]
CL8  0.01uF/10V/X5R/10%  [0402C]
CL9  0.1uF/16V/X7R/10%  [0402C]
CL10  0.1uF/16V/X7R/10%  [0402C]
CL11  0.1uF/16V/X7R/10%  [0402C]
CL12  10uF/10V/X7R/10%  [0402C]
CL13  0.1uF/16V/X7R/10%  [0402C]
CL14  0.1uF/16V/X7R/10%  [0402C]
CL15  1uF/16V/X7R/10%  [0402C]
CL17  1uF/16V/X7R/10%  [0402C]
CL18  0.1uF/16V/X7R/10%  [0402C]
FB9  4.7uH 400mA  [FB0805]
FBL1  BEAD  [0603L]
FBL2  BEAD  [0603L]
FBL3  BEAD  [0603L]
J16  HR911130C  [HR911130C]
R48  RES,2.37K 1%,0402  [R0402]
R49  RES,510,0402  [R0402]
R50  RES,510,0402  [R0402]
R209  0R,5%  [R0402]
RL10  10K,5%  [0402R]
RL11  10K,5%  [0402R]
RL14  10K,5%  [0402R]
RL15  10K,5%  [0402R]
RL16  10K,5%  [0402R]
RL17  10K,5%  [0402R]
RL18  10K,5%  [0402R]
RL19  10K,5%  [0402R]
RL20  10K,5%  [0402R]
RL21  10K,5%  [0402R]
U12  AR8035-AL1A  [QFN40]
Y2  25.000MHz  [CRYSTAL_5X3P2]
sheet 24 TRIG@LED
CAB73  0.1uF/25V/X7R/10%  [0402C]
CAB74  0.1uF/25V/X7R/10%  [0402C]
CAB75  0.1uF/25V/X7R/10%  [0402C]
CAB76  0.1uF/25V/X7R/10%  [0402C]
D12  GREEN  [0603LED]
D13  RED  [0603LED]
D14  SCHOTTKY,BAT54S  [SOT23]
D15  YELLOW  [0603LED]
D16  SCHOTTKY,BAT54S  [SOT23]
JA18  MMCX  [MMCX-TH1]
JA19  MMCX  [MMCX-TH1]
JA20  MMCX  [MMCX-TH1]
JA21  MMCX  [MMCX-TH1]
JA22  MMCX  [MMCX-TH1]
Q5  9014  [SOT_23]
Q6  9014  [SOT_23]
Q7  9014  [SOT_23]
R74  510R,1%  [R0402]
R75  510R,1%  [R0402]
R76  0R,1%  [R0402]
R77  33R,1%  [R0402]
R78  510R,1%  [R0402]
R79  510R,1%  [R0402]
R80  510R,1%  [R0402]
R81  510R,1%  [R0402]
R82  0R,1%  [R0402]
R83  33R,1%  [R0402]
R84  499R,1%  [R0402]
R85  499R,1%  [R0402]
R86  499R,1%  [R0402]
R87  499R,1%  [R0402]
R88  33R,1%  [R0402]
R89  0R,1%  [R0402]
R90  50R,1%  [R0402]
R91  33R,1%  [R0402]
R92  50R,1%  [R0402]
R93  33R,1%  [R0402]
R94  240R,1%  [R0402]
SWC1  A6FR-2104  [A6FR-2104]
SWC2  SIP2  [SIP2]
SWC3  SIP2  [SIP2]
SWC4  SWP1  [SWP1]
sheet 25 POWER00
C105  100pF/10V/X5R/20%  [C0603]
C106  100pF/10V/X5R/20%  [C0603]
C107  100pF/10V/X5R/20%  [C0603]
CIN1  22uF/25V/X5R/20%  [7343-43]
CIN2  22uF/25V/X5R/20%  [7343-43]
CIN3  22uF/25V/X5R/20%  [7343-43]
CIN4  22uF/25V/X5R/20%  [7343-43]
CIN5  100uF/25V/X5R/20%  [7343-43]
COUT1  100uF/16V/X5R/20%  [7343-43]
COUT2  100uF/16V/X5R/20%  [7343-43]
COUT3  100uF/16V/X5R/20%  [7343-43]
COUT4  100uF/16V/X5R/20%  [7343-43]
COUT5  100nF/10V/X5R/20%  [C0603]
RP1  2K 1%  [0402R]
RP2  0R 1%  [0402R]
RP3  0R, 1%  [0402R]
RP4  0R, 1%  [0402R]
RP5  0R, 1%  [0402R]
RP6  0R, 1%  [0402R]
RP7  0R, 1%  [0402R]
RP8  0R, 1%  [0402R]
RP9  0R, 1%  [0402R]
RP10  100K 1%  [0402R]
RP11  0R, 1%  [0402R]
RP12  10K 1%  [0402R]
TP1  PGOOD1  [PAD-50SMT]
U19  LTM4644EY#PBF  [4644_BGA]
sheet 26 POWER01
CIN6  22uF/25V/X5R/20%  [7343-43]
CIN7  22uF/25V/X5R/20%  [7343-43]
CIN8  22uF/25V/X5R/20%  [7343-43]
CIN9  22uF/25V/X5R/20%  [7343-43]
CIN10  22uF/25V/X5R/20%  [7343-43]
CIN11  22uF/25V/X5R/20%  [7343-43]
COUT9  220uF/4V/X5R/20%  [C1206]
COUT10  220uF/4V/X5R/20%  [C1206]
COUT11  220uF/4V/X5R/20%  [C1206]
COUT12  220uF/10V/X5R/20%  [7343-43]
COUT13  220uF/10V/X5R/20%  [7343-43]
COUT14  220uF/10V/X5R/20%  [7343-43]
FBP1  BLM21PG121SN1  [0805L]
FBP2  BLM21PG121SN1  [0805L]
FBP7  BLM21PG121SN1  [0805L]
FBP8  BLM21PG121SN1  [0805L]
FBP9  BLM21PG121SN1  [0805L]
FBP10  BLM21PG121SN1  [0805L]
FBP17  BLM21PG121SN1  [0805L]
FBP18  BLM21PG121SN1  [0805L]
FBP19  BLM21PG121SN1  [0805L]
FBP20  BLM21PG121SN1  [0805L]
R95  4.99K,1%  [R0603]
R96  0R,1%  [R0603]
R97  0R,1%  [R0402]
R99  10K,1%  [R0603]
R100  2K,1%  [R0603]
R101  221R,1%  [R0603]
R102  0R,1%  [R0402]
R104  10K,1%  [R0603]
U20  MYMGK00504ERSR  [LGA_75]
U21  MYMGK00504ERSR  [LGA_75]
sheet 27 POWER02
C108  22UF/25V/X5R/20%  [C1206]
C109  22UF/25V/X5R/20%  [C1206]
C110  22UF/25V/X5R/20%  [C1206]
D19  SMBJ22A  [SMB]
EC1  16SVPK330M  [EC-E7]
FB15  PPTC_10A  [7343FUSE]
H7  HOLE  [HOLE_D2_5]
H8  HOLE  [HOLE_D2_5]
H9  HOLE  [HOLE_D2_5]
H10  HOLE  [HOLE_D2_5]
H11  HOLE  [HOLE_D2_5]
H12  HOLE  [HOLE_D2_5]
H13  HOLE  [HOLE_D2_5]
H14  HOLE  [HOLE_D2_5]
H15  HOLE  [HOLE_D2_5]
H16  HOLE  [HOLE_D2_5]
H17  HOLE  [HOLE_D2_5]
H18  HOLE  [HOLE_D2_5]
H19  HOLE  [HOLE_D2_5]
H20  HOLE  [HOLE_D2_5]
H21  HOLE  [HOLE_D2_5]
H22  HOLE  [HOLE_D2_5]
H23  HOLE  [HOLE_D2_5]
H24  HOLE  [HOLE_D2_5]
H25  HOLE  [HOLE_D2_5]
H26  HOLE  [HOLE_D2_5]
H27  HOLE  [HOLE_D2_5]
H28  HOLE  [HOLE_D2_5]
H29  HOLE  [HOLE_D2_5]
H30  HOLE  [HOLE_D2_5]
H31  HOLE  [HOLE_D2_5]
H32  HOLE  [HOLE_D2_5]
H33  HOLE  [HOLE_D2_5]
H34  HOLE  [HOLE_D2_5]
H35  HOLE  [HOLE_D2_5]
H36  HOLE  [HOLE_D2_5]
H37  HOLE  [HOLE_D2_5]
H38  HOLE  [HOLE_D2_5]
H39  HOLE  [HOLE_D2_5]
H40  HOLE  [HOLE_D2_5]
H41  HOLE  [HOLE]
H42  HOLE  [HOLE]
H43  HOLE  [HOLE]
H44  HOLE  [HOLE]
H45  HOLE  [HOLE]
H46  HOLE  [HOLE]
H47  HOLE  [HOLE]
H48  HOLE  [HOLE]
J19  HX-TJC3-2PIN-WHITE  [HX-TJC3-2PIN-WHITE]
J20  HX-TJC3-2PIN-WHITE  [HX-TJC3-2PIN-WHITE]
J21  HX-TJC3-2PIN-WHITE  [HX-TJC3-2PIN-WHITE]
J22  HX-TJC3-2PIN-WHITE  [HX-TJC3-2PIN-WHITE]
J23  POWER_JACK_ADAPTER  [POWERA]
J24  HX-TJC3-2PIN-WHITE  [HX-TJC3-2PIN-WHITE]
J25  HX-TJC3-2PIN-WHITE  [HX-TJC3-2PIN-WHITE]
J26  POWER HEADER-6P-4P2MM  [POWER_HEADER-6P-4P2MM]
J27  HX-TJC3-2PIN-WHITE  [HX-TJC3-2PIN-WHITE]
J28  HX-TJC3-2PIN-WHITE  [HX-TJC3-2PIN-WHITE]
J32  022112032  [022112032]
JFA6  HX-TJC3-2PIN-WHITE  [HX-TJC3-2PIN-WHITE]
P3  HOLE_D2p5  [HOLE_D2_5]
P4  HOLE_D2p5  [HOLE_D2_5]
P5  HOLE_D2p5  [HOLE_D2_5]
P7  HOLE_D2p5  [HOLE_D2_5]
P8  HOLE_D2p5  [HOLE_D2_5]
P9  HOLE_D2p5  [HOLE_D2_5]
P11  HOLE_D2p5  [HOLE_D2_5]
P12  HOLE_D2p5  [HOLE_D2_5]
P13  HOLE_D2p5  [HOLE_D2_5]
P14  HOLE_D2p5  [HOLE_D2_5]
RP129  1K,1%  [0402R]
SP1  HEADER 2  [sip2_HV]
U22  BNX016-01  [bnx016-01]

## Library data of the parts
C43-C48 C53 C57 C58 C108-C110 CAA4 CAA9 CAA14 CAA19 CAA24 CAA29 CAA34 CAA39 CAB40 CAB42 CAB46 CAB48-CAB76 CL7-CL15 CL17 CL18 = CAP
JA7-JA16 = BNC_3
LAB32-LAB34 LAB37-LAB39 LAB41-LAB56 R95-R97 R99-R102 R104 RAA2-RAA4 RAA6-RAA8 RAA10-RAA12 RAA14-RAA16 RAA18-RAA20 RAA22-RAA24 RAA26-RAA28 RAA30-RAA32 RAB26-RAB28 RAB30-RAB32 RL10 RL11 RL14-RL21 RP129 = RES
TAB7-TAB16 = TCM1_83X_P_1: REUSE_ANNOTATE: TRUE
FB6 FB7 FB9 = BLM21PG121SN1D
J40 = SFP+_SINGLEMODULE
R48-R50 R74-R76 R78-R82 R84-R87 R184-R191 R209 = RES-H
FBL1-FBL3 = INDUCTOR
J16 = HR911130C
U12 = AR8035-AL1A
Y2 = CRYSTAL
D12 D13 D15 = LED
D14 D16 = SCHOTTKY,BAT54S
JA18-JA22 = BNC_3: REUSE_ANNOTATE: TRUE
Q5-Q7 = 1R1001_0
R77 R83 R88-R94 = RES,33R,0402
SWC1 = A6FR-2104
SWC2 SWC3 = B2S_0
SWC4 = SW_PB_SPST
C105-C107 = CAP1206: 1ST PART FIELD: 6.3V; 2ND PART FIELD: 0805-1206
CIN1-CIN4 CIN7 CIN8 CIN10 CIN11 = CAP1206: 1ST PART FIELD: 25V; 2ND PART FIELD: 0805-1206
CIN5 CIN6 CIN9 = CAP-SVPA-E7: 1ST PART FIELD: 25V
COUT1-COUT4 = CAP1206: 1ST PART FIELD: 6.3V; 2ND PART FIELD: 0805-1206; VOLTAGE: 16V
COUT5 = CAP1206: 1ST PART FIELD: 6.3V; 2ND PART FIELD: 0805-1206; VOLTAGE: 6.3V
RP1-RP12 = R: REUSE_ANNOTATE: TRUE
TP1 = E-100SMT
U19 = LTM4644EY#PBF_2
COUT9-COUT11 = CAP1206: 1ST PART FIELD: 6.3V; 2ND PART FIELD: 0805-1206; VOLTAGE: 4V
COUT12-COUT14 = CAP1206: 1ST PART FIELD: 6.3V; 2ND PART FIELD: 0805-1206; VOLTAGE: 10V
FBP1 FBP2 FBP7-FBP10 FBP17-FBP20 = BLM21PG121SN1: REUSE_ANNOTATE: TRUE
U20 U21 = MYMGK00504ERSR_1
D19 = DIODE_TVS
EC1 = 16SVPK330M
FB15 = JK250-800U
H7-H40 = HOLE_v2
H41-H48 = HOLE
J19-J22 J24 J25 J27 J28 JFA6 = HX-TJC3-2PIN-WHITE
J23 = POWER_JACK_ADAPTER
J26 = POWER_HEADER-6P-4P2MM_0
J32 = 022112032
P3-P5 P7-P9 P11-P14 = HOLE_2p5
SP1 = HEADER_2
U22 = BNX016-01

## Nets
+1.8V: FBP1.1 FBP2.1 R99.2 ; also on sheet 20 21 27
+3.3V: C43.1 C44.1 D14.2 D16.2 FB6.1 FB7.1 FBL2.1 FBL3.1 FBP7.1 FBP8.1 R74.1 R78.1 R80.1 R104.2 R184.2 R186.2 R187.2 R188.2 R189.2 R190.2 R191.2 RP129.1 ; also on sheet 20 21 23 24 25 27 28
AVDD33: CL15.2 FBL2.2 U12.14(AVDD33)
AVDDL: CL10.2 CL11.2 CL13.2 FBL1.2 U12.6(AVDDL) U12.11(AVDDL2) U12.17(AVDDL3)
DGND: C43.2 C44.2 C45.2 C46.2 C47.2 C48.2 C53.2 C57.1 C58.1 C105.2 C106.2 C107.2 C109.2 C110.2 CAB73.1 CAB75.1 CAB76.1 CIN1.2 CIN2.2 CIN3.2 CIN4.2 CIN5.2 CIN6.2 CIN7.2 CIN8.2 CIN9.2 CIN10.2 CIN11.2 CL7.1 CL8.1 CL9.1 CL10.1 CL11.1 CL12.1 CL13.1 CL14.1 CL15.1 CL17.1 CL18.1 COUT1.2 COUT2.2 COUT3.2 COUT4.2 COUT5.2 COUT9.2 COUT10.2 COUT11.2 COUT12.2 COUT13.2 COUT14.2 D14.1 D16.1 EC1.2 H7.1 H8.1 H9.1 H10.1 H11.1 H12.1 H13.1 H14.1 H15.1 H16.1 H17.1 H18.1 H19.1 H20.1 H21.1 H22.1 H23.1 H24.1 H25.1 H26.1 H27.1 H28.1 H29.1 H30.1 H31.1 H32.1 H33.1 H34.1 H35.1 H36.1 H37.1 H38.1 H39.1 H40.1 H41.1(GND8) H41.2(GND6) H41.3(GND1) H41.4(GND5) H41.5(GND9) H41.6(GND2) H41.7(GND4) H41.8(GND3) H41.9(GND7) H42.1(GND8) H42.2(GND6) H42.3(GND1) H42.4(GND5) H42.5(GND9) H42.6(GND2) H42.7(GND4) H42.8(GND3) H42.9(GND7) H43.1(GND8) H43.2(GND6) H43.3(GND1) H43.4(GND5) H43.5(GND9) H43.6(GND2) H43.7(GND4) H43.8(GND3) H43.9(GND7) H44.1(GND8) H44.2(GND6) H44.3(GND1) H44.4(GND5) H44.5(GND9) H44.6(GND2) H44.7(GND4) H44.8(GND3) H44.9(GND7) H45.1(GND8) H45.2(GND6) H45.3(GND1) H45.4(GND5) H45.5(GND9) H45.6(GND2) H45.7(GND4) H45.8(GND3) H45.9(GND7) H46.1(GND8) H46.2(GND6) H46.3(GND1) H46.4(GND5) H46.5(GND9) H46.6(GND2) H46.7(GND4) H46.8(GND3) H46.9(GND7) H47.1(GND8) H47.2(GND6) H47.3(GND1) H47.4(GND5) H47.5(GND9) H47.6(GND2) H47.7(GND4) H47.8(GND3) H47.9(GND7) H48.1(GND8) H48.2(GND6) H48.3(GND1) H48.4(GND5) H48.5(GND9) H48.6(GND2) H48.7(GND4) H48.8(GND3) H48.9(GND7) J16.10(GND3) J16.15(GND1) J16.16(GND2) J19.2 J20.2 J21.2 J22.2 J24.2 J25.2 J27.2 J28.2 J32.1 J40.1(VEET) J40.10(VEER) J40.11(VEER) J40.14(VEER) J40.17(VEET) J40.20(VEET) J40.21(GND1) J40.22(GND2) J40.23(GND3) J40.24(GND4) J40.25(GND5) J40.26(GND6) J40.27(GND7) J40.28(GND8) J40.29(GND9) J40.30(GND10) J40.31(GND11) JA7.2(SHIELD1) JA7.3(SHIELD2) JA7.4(SHIELD3) JA7.5(SHIELD4) JA8.2(SHIELD1) JA8.3(SHIELD2) JA8.4(SHIELD3) JA8.5(SHIELD4) JA9.2(SHIELD1) JA9.3(SHIELD2) JA9.4(SHIELD3) JA9.5(SHIELD4) JA10.2(SHIELD1) JA10.3(SHIELD2) JA10.4(SHIELD3) JA10.5(SHIELD4) JA11.2(SHIELD1) JA11.3(SHIELD2) JA11.4(SHIELD3) JA11.5(SHIELD4) JA12.2(SHIELD1) JA12.3(SHIELD2) JA12.4(SHIELD3) JA12.5(SHIELD4) JA13.2(SHIELD1) JA13.3(SHIELD2) JA13.4(SHIELD3) JA13.5(SHIELD4) JA14.2(SHIELD1) JA14.3(SHIELD2) JA14.4(SHIELD3) JA14.5(SHIELD4) JA15.2(SHIELD1) JA15.3(SHIELD2) JA15.4(SHIELD3) JA15.5(SHIELD4) JA16.2(SHIELD1) JA16.3(SHIELD2) JA16.4(SHIELD3) JA16.5(SHIELD4) JA18.2(SHIELD1) JA18.3(SHIELD2) JA18.4(SHIELD3) JA18.5(SHIELD4) JA19.2(SHIELD1) JA19.3(SHIELD2) JA19.4(SHIELD3) JA19.5(SHIELD4) JA20.2(SHIELD1) JA20.3(SHIELD2) JA20.4(SHIELD3) JA20.5(SHIELD4) JA21.2(SHIELD1) JA21.3(SHIELD2) JA21.4(SHIELD3) JA21.5(SHIELD4) JA22.2(SHIELD1) JA22.3(SHIELD2) JA22.4(SHIELD3) JA22.5(SHIELD4) JFA6.2 P3.1 P4.1 P5.1 P7.1 P8.1 P9.1 P11.1 P12.1 P13.1 P14.1 Q5.2(E) Q6.2(E) Q7.2(E) R48.1 R49.2 R50.2 R84.1 R85.1 R86.1 R87.1 R90.2 R92.2 R94.2 R96.2 R101.2 R185.2 RAA3.2 RAA4.2 RAA7.2 RAA8.2 RAA11.2 RAA12.2 RAA15.2 RAA16.2 RAA19.2 RAA20.2 RAA23.2 RAA24.2 RAA27.2 RAA28.2 RAA31.2 RAA32.2 RAB27.2 RAB28.2 RAB31.2 RAB32.2 RL16.2 RL17.2 RL18.2 RL19.2 RL20.2 RP2.2 SWC4.2 TAB7.1(PRI1) TAB7.2(PRI2) TAB7.5(NC) TAB8.1(PRI1) TAB8.2(PRI2) TAB8.5(NC) TAB9.1(PRI1) TAB9.2(PRI2) TAB9.5(NC) TAB10.1(PRI1) TAB10.2(PRI2) TAB10.5(NC) TAB11.1(PRI1) TAB11.2(PRI2) TAB11.5(NC) TAB12.1(PRI1) TAB12.2(PRI2) TAB12.5(NC) TAB13.1(PRI1) TAB13.2(PRI2) TAB13.5(NC) TAB14.1(PRI1) TAB14.2(PRI2) TAB14.5(NC) TAB15.1(PRI1) TAB15.2(PRI2) TAB15.5(NC) TAB16.1(PRI1) TAB16.2(PRI2) TAB16.5(NC) U12.41(GDN_PAD) U19.A4(GND1) U19.A5(GND2) U19.B1(GND3) U19.B2(GND4) U19.C5(GND5) U19.D3(GND6) U19.D4(GND7) U19.D5(GND8) U19.E1(GND9) U19.E2(GND10) U19.F5(GND11) U19.F7(SGND) U19.G3(GND12) U19.G4(GND13) U19.G5(GND14) U19.H1(GND15) U19.H2(GND16) U19.J5(GND17) U19.K3(GND18) U19.K4(GND19) U19.L1(GND20) U19.L2(GND21) U20.3(GND9) U20.8(GND10) U20.9(GND11) U20.10(GND12) U20.13(GND14) U20.14(GND13) U20.15(GND0) U20.16(GND1) U20.17(GND2) U20.18(GND3) U20.19(GND4) U20.20(GND5) U20.21(GND6) U20.22(GND7) U20.23(GND8) U21.3(GND9) U21.8(GND10) U21.9(GND11) U21.10(GND12) U21.13(GND14) U21.14(GND13) U21.15(GND0) U21.16(GND1) U21.17(GND2) U21.18(GND3) U21.19(GND4) U21.20(GND5) U21.21(GND6) U21.22(GND7) U21.23(GND8) U22.5(CG3) U22.6(CG2) U22.7(CG1) ; also on sheet 13 14 15 16 18 20 21 23 24 25 27 28
DVDDL: CL7.2 CL8.2 CL9.2 FB9.1 FBL1.1 U12.38(DVDDL)
VCC_5V: COUT1.1 COUT2.1 COUT3.1 COUT4.1 RP12.1 U19.A1(VOUT1A) U19.A2(VOUT1B) U19.A3(VOUT1C) U19.C1(VOUT2A) U19.D1(VOUT2B) U19.D2(VOUT2C) U19.F1(VOUT3A) U19.G1(VOUT3B) U19.G2(VOUT3C) U19.J1(VOUT4A) U19.K1(VOUT4B) U19.K2(VOUT4C) ; also on sheet 16 18 20 28
VCC_12V: C109.1 C110.1 CIN1.1 CIN2.1 CIN3.1 CIN4.1 CIN5.1 CIN6.1 CIN7.1 CIN8.1 CIN9.1 CIN10.1 CIN11.1 EC1.1 J19.1 J20.1 J21.1 J22.1 J24.1 J25.1 J27.1 J28.1 J32.2 RP3.1 RP4.1 RP5.1 RP6.1 U19.B3(VIN1A) U19.B4(VIN1B) U19.B5(SVin1) U19.E3(VIN2A) U19.E4(VIN2B) U19.E5(SVin2) U19.H3(VIN3A) U19.H4(VIN3B) U19.H5(SVin3) U19.L3(VIN4A) U19.L4(VIN4B) U19.L5(SVin4) U20.1(VIN1) U20.2(VIN2) U21.1(VIN1) U21.2(VIN2) U22.8(CB) ; also on sheet 28
VCCO_89: FBP9.1 FBP10.1 ; also on sheet 16
VCCO_501: FBP17.1 FBP18.1 ; also on sheet 16
VCCO_502: FBP19.1 FBP20.1 ; also on sheet 16
VDD33: CL12.2 CL14.2 FBL3.2 U12.3(VDD33)
VDDH: CL17.2 CL18.2 RL10.2 RL11.2 RL14.2 RL15.2 RL21.2 U12.8(VDDH_REG) U12.27(VDDIO_REG)
BANK129_MGT_RX0_N: J40.12(RDN) ; also on sheet 17
BANK129_MGT_RX0_P: J40.13(RDP) ; also on sheet 17
BANK129_MGT_TX0_N: J40.19(TDN) ; also on sheet 17
BANK129_MGT_TX0_P: J40.18(TDP) ; also on sheet 17
CLKIN0_N: CAB75.2 ; also on sheet 17
CLKIN0_P: CAB74.2 ; also on sheet 17
INTVCC1: RP10.1 U19.B6(MODE1) U19.C4(INTVCC1) U19.E6(MODE2) U19.F4(INTVCC2) U19.H6(MODE3) U19.J4(INTVCC3) U19.K5(INTVCC4) U19.L6(MODE4)
PHY_LED_1000: J16.11(LEDG+) RL15.1 U12.22(LED_1000)
PHY_LED_ACT: J16.14(LEDY+) RL18.1 U12.21(LED_ACT)
PHY_MDC: U12.40(MDC) ; also on sheet 17
PHY_MDINT: RL11.1 U12.20(INT)
PHY_MDIO: RL10.1 U12.39(MIDO) ; also on sheet 17
PHY_RX_CLK: RL21.1 U12.31(RX_CLK) ; also on sheet 17
PHY_RX_CTRL: RL17.1 U12.30(RX_DV) ; also on sheet 17
PHY_RXD0: RL20.1 U12.29(RXD0) ; also on sheet 17
PHY_RXD1: RL19.1 U12.28(RXD1) ; also on sheet 17
PHY_RXD2: RL16.1 U12.26(RXD2) ; also on sheet 17
PHY_RXD3: RL14.1 U12.25(RXD3) ; also on sheet 17
PHY_TRXN0: J16.3(T1-) U12.10(TRXN0)
PHY_TRXN1: J16.7(T2-) U12.13(TRXN1)
PHY_TRXN2: J16.6(T3-) U12.16(TRXN2)
PHY_TRXN3: J16.9(T4-) U12.19(TRXN3)
PHY_TRXP0: J16.2(T1+) U12.9(TRXP0)
PHY_TRXP1: J16.4(T2+) U12.12(TRXP1)
PHY_TRXP2: J16.5(T3+) U12.15(TRXP2)
PHY_TRXP3: J16.8(T4+) U12.18(TRXP3)
PHY_TX_CLK: U12.33(GTX_CLK) ; also on sheet 17
PHY_TX_CTRL: U12.32(TX_EN) ; also on sheet 17
PHY_TXD0: U12.34(TXD0) ; also on sheet 17
PHY_TXD1: U12.35(TXD1) ; also on sheet 17
PHY_TXD2: U12.36(TXD2) ; also on sheet 17
PHY_TXD3: U12.37(TXD3) ; also on sheet 17
PHY_XTAL_IN: C57.2 U12.5(XTLI) Y2.2
PHY_XTAL_OUT: C58.2 U12.4(XTLO) Y2.1
PS_DONE: R75.2 ; also on sheet 17
PS_ERR_STAT: R81.2 ; also on sheet 17
PS_ERROR: R79.2 ; also on sheet 17
PS_MODE0: SWC3.1 ; also on sheet 17
PS_MODE1: SWC2.1 ; also on sheet 17
PS_MODE2: SWC1.3 ; also on sheet 17
PS_MODE3: SWC1.1 ; also on sheet 17
PS_POR: R209.1 ; also on sheet 17
PS_POR_B: R209.2 U12.1(RESTN)
RX_00_N: CAB49.1 LAB42.2 ; also on sheet 19
RX_00_P: CAB51.1 LAB42.1 ; also on sheet 19
RX_01_N: CAB52.1 LAB44.2 ; also on sheet 19
RX_01_P: CAB54.1 LAB44.1 ; also on sheet 19
RX_02_N: CAB55.1 LAB46.2 ; also on sheet 19
RX_02_P: CAB57.1 LAB46.1 ; also on sheet 19
RX_03_N: CAB58.1 LAB48.2 ; also on sheet 19
RX_03_P: CAB60.1 LAB48.1 ; also on sheet 19
RX_04_N: CAB61.1 LAB50.2 ; also on sheet 19
RX_04_P: CAB63.1 LAB50.1 ; also on sheet 19
RX_05_N: CAB64.1 LAB52.2 ; also on sheet 19
RX_05_P: CAB66.1 LAB52.1 ; also on sheet 19
RX_06_N: CAB67.1 LAB54.2 ; also on sheet 19
RX_06_P: CAB69.1 LAB54.1 ; also on sheet 19
RX_07_N: CAB70.1 LAB56.2 ; also on sheet 19
RX_07_P: CAB72.1 LAB56.1 ; also on sheet 19
SFP_VCCRX: C45.1 C46.1 FB6.2 J40.15(VCCR)
SFP_VCCTX: C47.1 C48.1 FB7.2 J40.16(VCCT)
SYS_CLK_OUT_N: CAB76.2 ; also on sheet 17
SYS_CLK_OUT_P: R93.2 R94.1 ; also on sheet 17
SYS_RESET#: SWC4.1 ; also on sheet 17
SYSREF_IN_N: CAB73.2 ; also on sheet 17
SYSREF_IN_P: R89.2 ; also on sheet 17
TRIG_IN: R76.1 ; also on sheet 19
TRIG_OUT: R82.1 ; also on sheet 19
TX_06_N: LAB32.2 LAB33.2 ; also on sheet 19
TX_06_P: LAB33.1 LAB34.2 ; also on sheet 19
TX_07_N: LAB37.2 LAB38.2 ; also on sheet 19
TX_07_P: LAB38.1 LAB39.2 ; also on sheet 19
N22481429: C108.2 D19.1(ANODE) J23.2 J23.3 J26.4 J26.5 J26.6 U22.3(PSG)
N22481433: FB15.1 J23.1 J26.1 J26.2 J26.3
N22481513: C108.1 SP1.1 U22.1(B)
N22481515: D19.2(CATHODE) FB15.2 SP1.2
N22533284: RP4.2 U19.F6(RUN2)
N22533286: RP5.2 U19.J6(RUN3)
N22533326: RP9.2 U19.F2(PGOOD3)
N22533328: RP7.1 RP8.1 RP9.1 RP10.2 RP11.1 TP1.1(A)
N22533342: COUT5.1 U19.A6(TRACK/SS1) U19.D6(TRACK/SS2) U19.G6(TRACK/SS3) U19.K6(TRACK/SS4)
N22533629: C105.1 U19.B7(COMP1) U19.E7(COMP2)
N22533693: RP1.1 U19.A7(FB1) U19.D7(FB2) U19.G7(FB3) U19.J7(FB4)
N22533770: RP3.2 U19.C6(RUN1)
N22533812: RP6.2 U19.K7(RUN4)
N22533845: RP7.2 U19.C3(PGOOD1)
N22533851: RP8.2 U19.C2(PGOOD2)
N22533867: RP11.2 U19.J2(PGOOD4)
N22533883: C106.1 U19.H7(COMP3)
N22533912: RP12.2 U19.F3(TEMP)
N22533999: C107.1 U19.L7(COMP4)
N22534068: RP1.2 RP2.1
N22535757: COUT9.1 COUT10.1 COUT11.1 FBP1.2 FBP2.2 R97.2 U20.6(VOUT1) U20.7(VOUT2)
N22535954: COUT12.1 COUT13.1 COUT14.1 FBP7.2 FBP8.2 FBP9.2 FBP10.2 FBP17.2 FBP18.2 FBP19.2 FBP20.2 R102.2 U21.6(VOUT1) U21.7(VOUT2)
N22536146: R95.2 R96.1
N22536167: R95.1 U20.4(Trim)
N22536169: R97.1 U20.5(Sense)
N22536187: R99.1 U20.11(PWGOOD)
N22536481: R100.2 R101.1
N22536506: R100.1 U21.4(Trim)
N22536508: R102.1 U21.5(Sense)
N22536526: R104.1 U21.11(PWGOOD)
N22545864: LAB32.1 TAB7.4(SE)
N22545929: CAB40.1 TAB7.3(PR_D)
N22545941: CAB40.2 RAB26.1 RAB27.1
N22545947: CAB42.1 RAB26.2 RAB28.1
N22545953: CAB42.2 JA7.1(CENTER)
N22545955: LAB34.1 TAB7.6(SE_D)
N22546147: LAB37.1 TAB8.4(SE)
N22546214: CAB46.1 TAB8.3(PR_D)
N22546226: CAB46.2 RAB30.1 RAB31.1
N22546232: CAB48.1 RAB30.2 RAB32.1
N22546238: CAB48.2 JA8.1(CENTER)
N22546240: LAB39.1 TAB8.6(SE_D)
N22696156: CAB49.2 LAB41.2 TAB9.4(SE)
N22696251: CAA4.1 JA9.1(CENTER)
N22696263: CAA4.2 RAA2.1 RAA3.1
N22696269: CAB50.2 RAA2.2 RAA4.1
N22696275: CAB50.1 TAB9.3(PR_D)
N22696283: CAB51.2 LAB41.1 TAB9.6(SE_D)
N22696463: CAB52.2 LAB43.2 TAB10.4(SE)
N22696550: CAA9.1 JA10.1(CENTER)
N22696562: CAA9.2 RAA6.1 RAA7.1
N22696568: CAB53.2 RAA6.2 RAA8.1
N22696574: CAB53.1 TAB10.3(PR_D)
N22696580: CAB54.2 LAB43.1 TAB10.6(SE_D)
N22697544: CAB55.2 LAB45.2 TAB11.4(SE)
N22697619: CAA14.1 JA11.1(CENTER)
N22697639: CAA14.2 RAA10.1 RAA11.1
N22697645: CAB56.2 RAA10.2 RAA12.1
N22697651: CAB56.1 TAB11.3(PR_D)
N22697657: CAB57.2 LAB45.1 TAB11.6(SE_D)
N22697841: CAB58.2 LAB47.2 TAB12.4(SE)
N22697916: CAA19.1 JA12.1(CENTER)
N22697918: CAA19.2 RAA14.1 RAA15.1
N22697942: CAB59.2 RAA14.2 RAA16.1
N22697948: CAB59.1 TAB12.3(PR_D)
N22697954: CAB60.2 LAB47.1 TAB12.6(SE_D)
N22698936: CAB61.2 LAB49.2 TAB13.4(SE)
N22699019: CAA24.1 JA13.1(CENTER)
N22699033: CAA24.2 RAA18.1 RAA19.1
N22699037: CAB62.2 RAA18.2 RAA20.1
N22699043: CAB62.1 TAB13.3(PR_D)
N22699049: CAB63.2 LAB49.1 TAB13.6(SE_D)
N22699217: CAB64.2 LAB51.2 TAB14.4(SE)
N22699300: CAA29.1 JA14.1(CENTER)
N22699302: CAA29.2 RAA22.1 RAA23.1
N22699318: CAB65.2 RAA22.2 RAA24.1
N22699324: CAB65.1 TAB14.3(PR_D)
N22699330: CAB66.2 LAB51.1 TAB14.6(SE_D)
N22700324: CAB70.2 LAB55.2 TAB16.4(SE)
N22700407: CAA39.1 JA16.1(CENTER)
N22700409: CAA39.2 RAA30.1 RAA31.1
N22700425: CAB71.2 RAA30.2 RAA32.1
N22700431: CAB71.1 TAB16.3(PR_D)
N22700437: CAB72.2 LAB55.1 TAB16.6(SE_D)
N22700663: CAB67.2 LAB53.2 TAB15.4(SE)
N22700760: CAA34.1 JA15.1(CENTER)
N22700762: CAA34.2 RAA26.1 RAA27.1
N22700790: CAB68.2 RAA26.2 RAA28.1
N22700796: CAB68.1 TAB15.3(PR_D)
N22700802: CAB69.2 LAB53.1 TAB15.6(SE_D)
N22703406: CAB74.1 R91.2 R92.1
N22703440: R88.2 R89.1 R90.1
N22704009: JA20.1(CENTER) R88.1
N22704037: JA21.1(CENTER) R91.1
N22704041: JA22.1(CENTER) R93.1
N22704055: D14.3 R76.2 R77.1
N22704067: D16.3 R82.2 R83.1
N22704077: JA18.1(CENTER) R77.2
N22704079: JA19.1(CENTER) R83.2
N22849015: JFA6.1 RP129.2
N23202933: J40.6(MOD_DEF0) R188.1
N23202934: J40.7(RATE_SELECT0) R189.1
N23202935: J40.8(LOS) R191.1
N23202936: J40.2(TX_FAULT) R184.1
N23202937: J40.3(TX_DISABLE) R185.1
N23202938: J40.5(MOD_DEF1) R187.1
N23202939: J40.9(RATE_SELECT1) R190.1
N23202940: J40.4(MOD_DEF2) R186.1
N23203094: R48.2 U12.7(RBIAS)
N23203096: J16.13(LEDY-) R50.1
N23203097: J16.12(LEDG-) R49.1
N23203100: FB9.2 U12.2(LX)
N23203101: C53.1 J16.1(COM)
N23203614: D13.2(CATHODE) Q6.3(C)
N23203615: D13.1(ANODE) R78.2
N23203616: Q7.1(B) R81.1
N23203617: R84.2 SWC1.2
N23203618: D15.2(CATHODE) Q7.3(C)
N23203619: D12.2(CATHODE) Q5.3(C)
N23203620: Q6.1(B) R79.1
N23203621: D12.1(ANODE) R74.2
N23203622: D15.1(ANODE) R80.2
N23203624: R87.2 SWC3.2
N23203625: R85.2 SWC1.4
N23203626: Q5.1(B) R75.1
N23203627: R86.2 SWC2.2

Not connected (* = marked no-connect by the designer): J16 17(NU17) 18(NU18); J26 7(P1)* 8(P2)*; J32 3; J40 A1(NC)* A2(NC)* A3(NC)* A4(NC)* A5(NC)* A6(NC)* A7(NC)* A8(NC)* A9(NC)* A10(NC)* A11(NC)*; U12 23(CLK_25M) 24(LED_10_100); U19 C7(CLKIN)* J3(CLKOUT)*; U20 12(ON/OFF)*; U21 12(ON/OFF)*

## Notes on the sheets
sheet 1
- DC_IN_12V
- LTM4644EY#PBF
- VCC5V/16A
- VCC1.8V/4A
- MYMGK00504ERSR
- VCC3.3V/4A
- MYMGK00504ERSR
- V3BEST
- RFSOM_EVM_REV12
- 01 POWER_TREE
sheet 2
- MODE[2]
- MODE[3]
- active low
- MODE[1]
- 等 长 要 求：组 内 等 长，等 长 误 差 正 负 10mil
- MODE[0]
- ADD[2]
- active high
- ADD[1]
- ADD[0]
- MODE[3:0]:
  1100: RGMII, PLLOFF, INT (Suggested)
  1110: RGMII, PLLON, INT
  PHY_ADDR:100(DEFAULT)
- Near PIN8
- Near PIN27
- Near LP5 to UE1
- Near PIN38
- Near PIN6 11 17
- V3BEST
- RFSOM_EVM_REV12
- 20 ETHERNET
sheet 3
- SFP+ Cage 74754-0101
- V3BEST
- RFSOM_EVM_REV12
- 19 QSFP
sheet 4
- select the screw thread plug connector
- Reserve the space for plug
  switch on panel by cable
- MOLEX:39-30-1060
- 布局尽量放置在一起
- V3BEST
- RFSOM_EVM_REV12
- 27 POWER02
sheet 5
- 1.8V
- Rtrim(kohm)=6/(Vout-0.6)
- 3.3V
- Rtrim(kohm)=6/(Vout-0.6)
- V3BEST
- RFSOM_EVM_REV12
- 26 POWER01
sheet 6
- 16A
- V3BEST
- RFSOM_EVM_REV12
- 25 POWER00
sheet 7
- TRIG_IN
- TRIG_OUT
- V3BEST
- RFSOM_EVM_REV12
- 24 TRIG@LED
sheet 8
- V3BEST
- RFSOM_EVM_REV12
- 14 RF_RX04
sheet 9
- V3BEST
- RFSOM_EVM_REV12
- 13 RF_RX03
sheet 10
- V3BEST
- RFSOM_EVM_REV112
- 12 RF_RX02
sheet 11
- V3BEST
- RFSOM_EVM_REV12
- 11 RF_RX01
sheet 12
- V3BEST
- RFSOM_EVM_REV12
- 10 RF_TX04
